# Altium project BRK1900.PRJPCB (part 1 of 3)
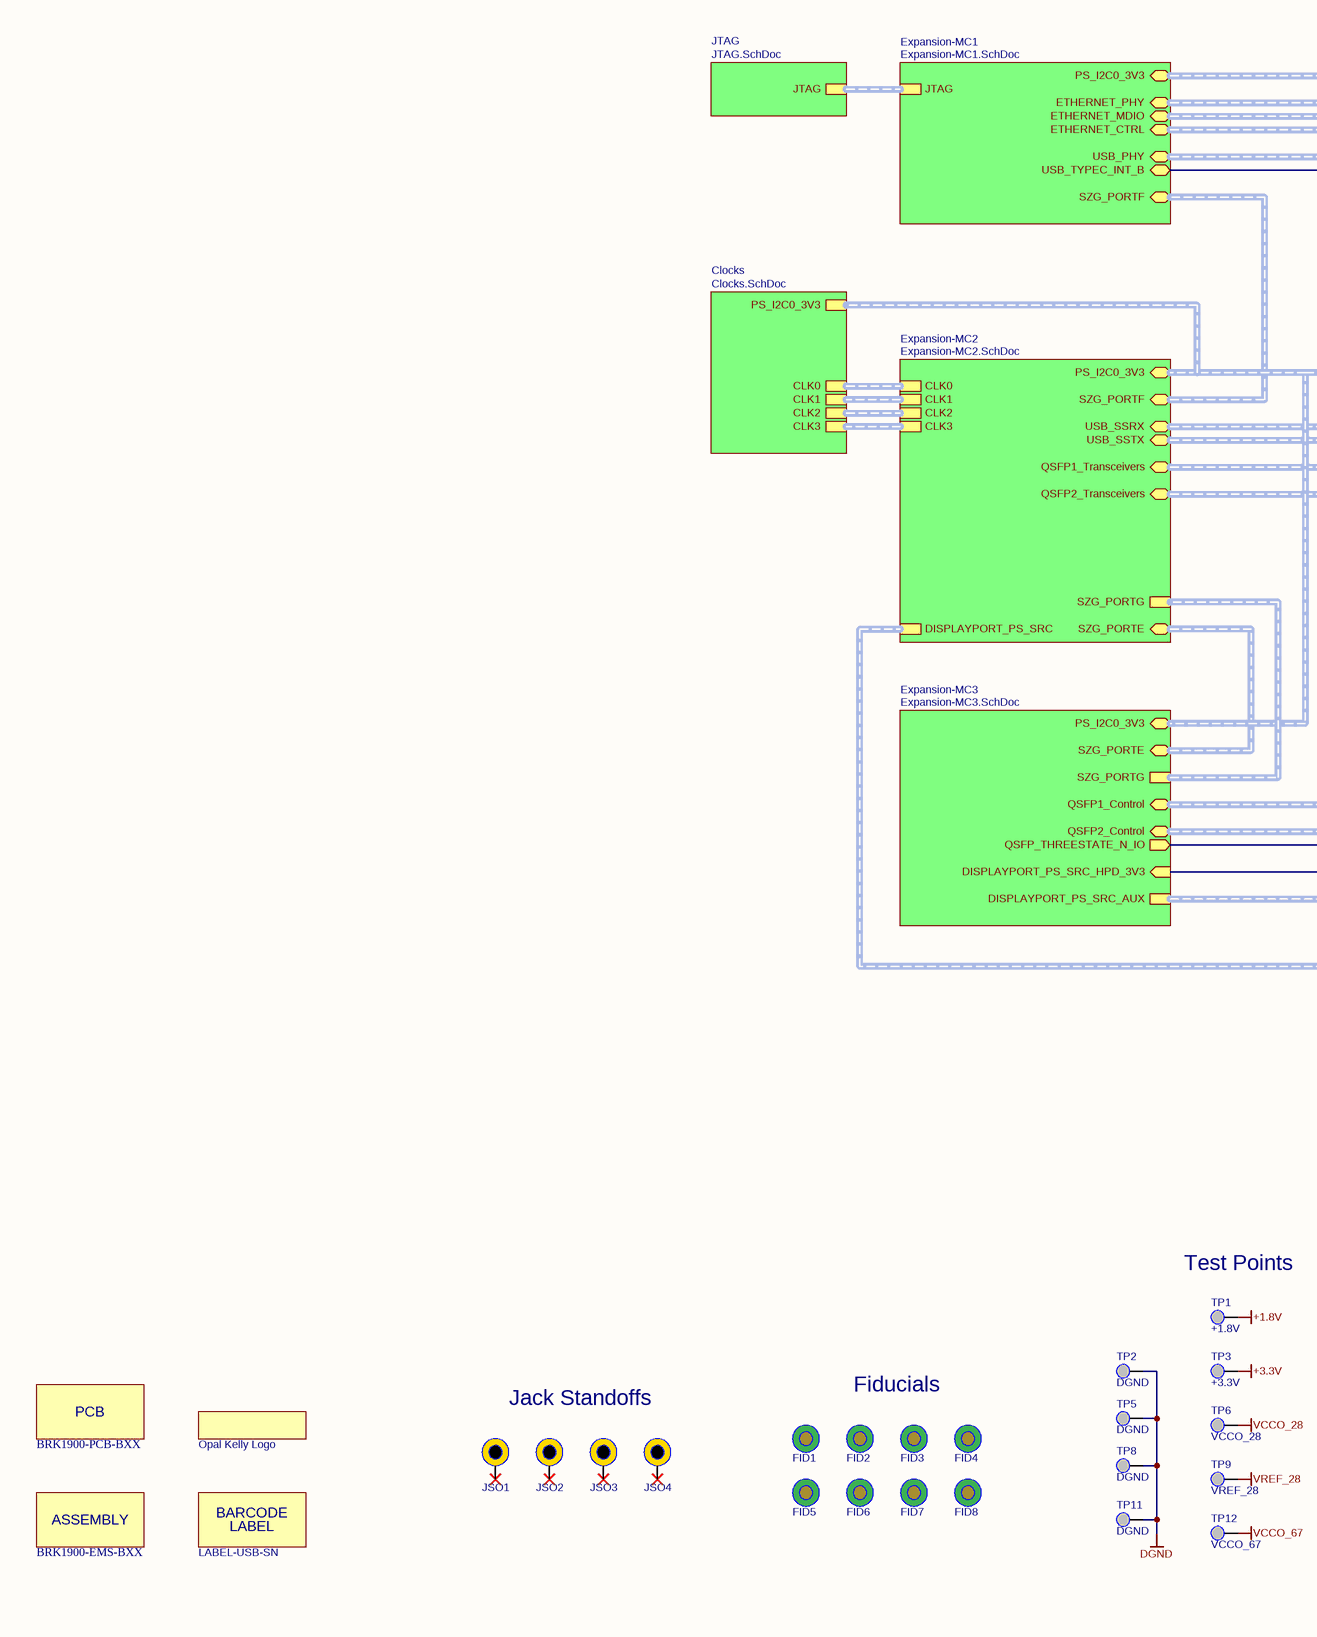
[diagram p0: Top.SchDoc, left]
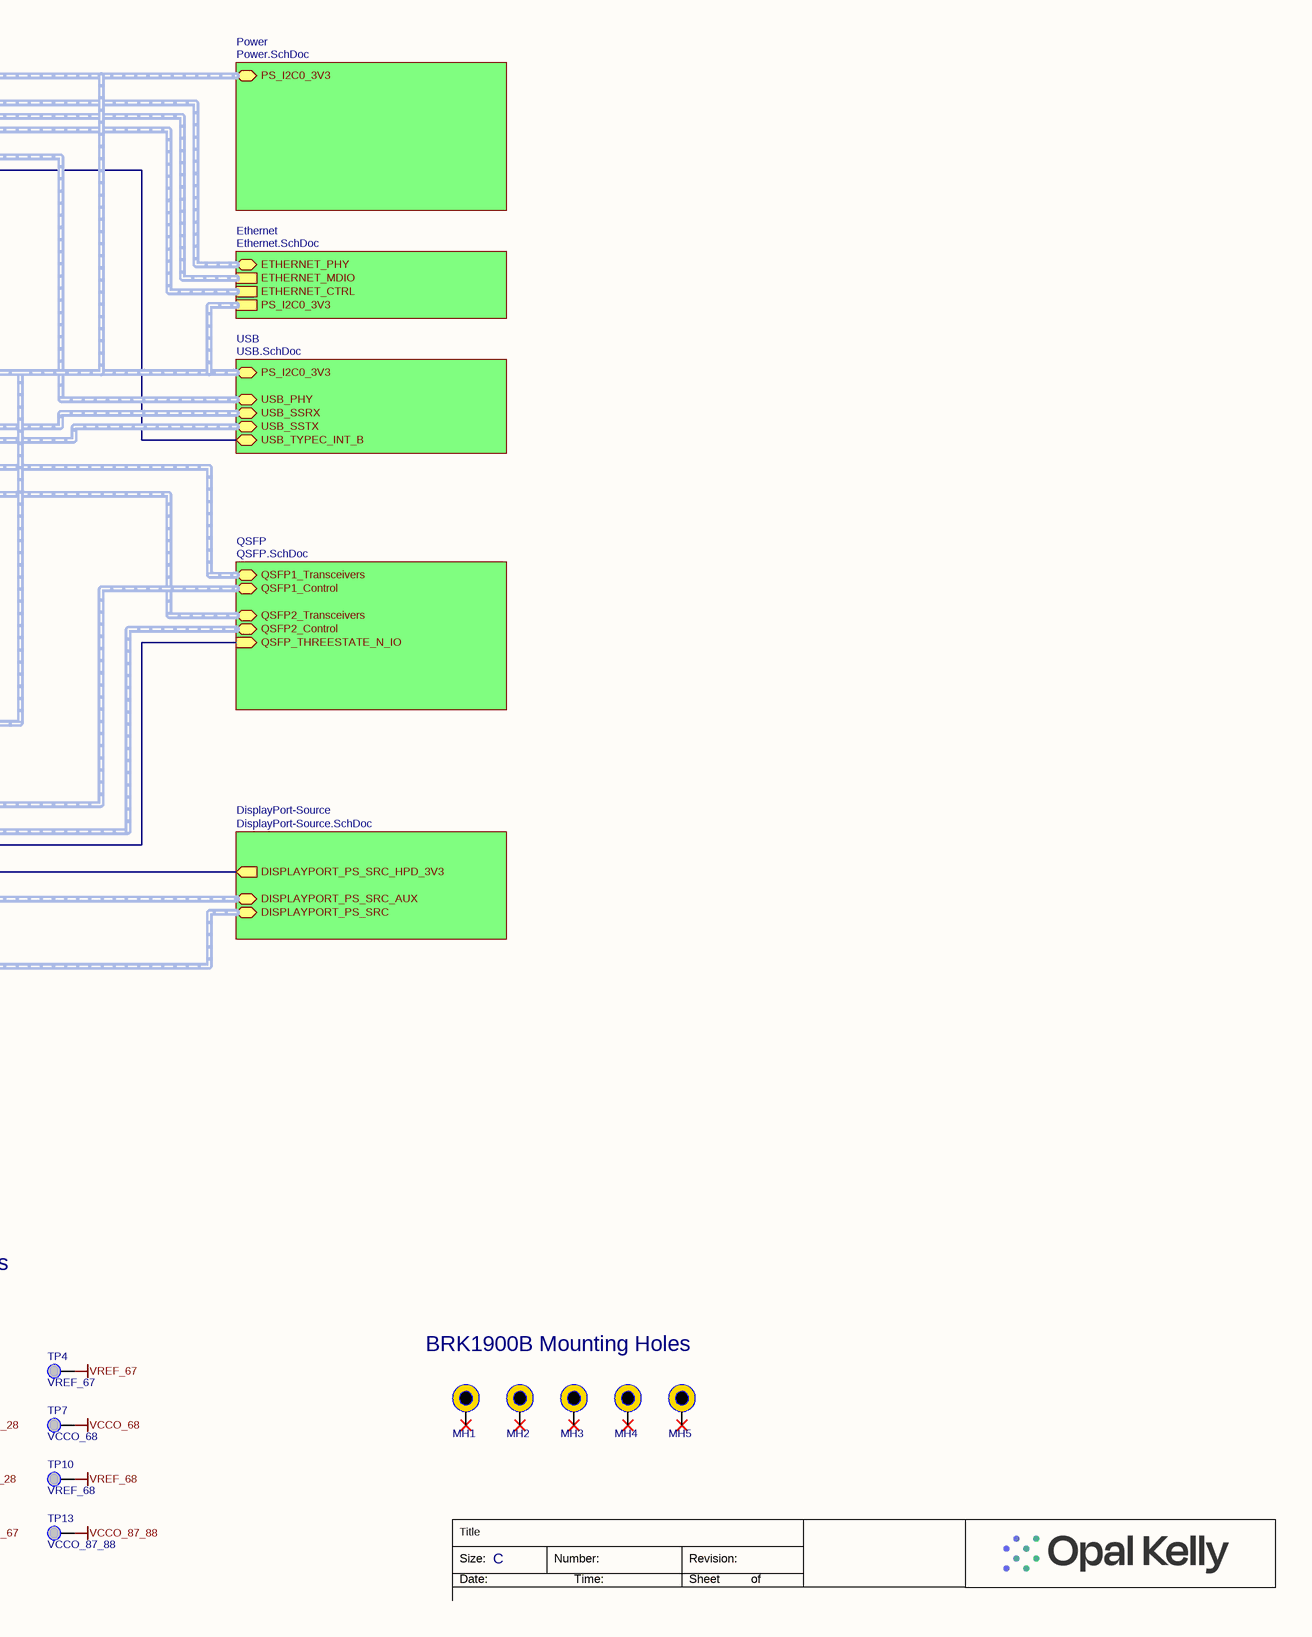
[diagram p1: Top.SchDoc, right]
BOM_Revision: 07; Part_Number: BRK1900; PCB_Revision: B
11 sheets, 459 parts. Net scope: hierarchical (ports join the sheet entries above them; power ports are global).
Board file: BRK1900.PcbDoc
Sheets:
  Top.SchDoc
    USB = USB.SchDoc
    QSFP = QSFP.SchDoc
    Expansion-MC1 = Expansion-MC1.SchDoc
    Expansion-MC2 = Expansion-MC2.SchDoc
    Expansion-MC3 = Expansion-MC3.SchDoc
    Power = Power.SchDoc
    Ethernet = Ethernet.SchDoc
    Clocks = Clocks.SchDoc
    DisplayPort-Source = DisplayPort-Source.SchDoc
    JTAG = JTAG.SchDoc

## Sheet Top.SchDoc: BRK1900 - Top Level
size C; Organization: Opal Kelly; Address1: 13500 SW 72nd Ave STE 100; Address2: Portland, OR  97223; Address3: 217.391.3724; Address4: http://www.opalkelly.com; DocumentNumber: 1; Revision: 1; SheetNumber: 1; SheetTotal: 11; PageSetup: Record=PageOptions¦CenterHorizontal=True¦CenterVertical=True¦PrintScale=0.52¦XCorrection=1.00¦YCorrection=1.00¦PrintKind=0¦BorderSize=5000000¦LeftOffset=0¦BottomOffset=0¦Orientation=2¦PaperLength=1000¦PaperWidth=1000¦Scale=100¦PaperSource=15¦PrintQuality=600¦MediaType=1¦DitherType=10¦PaperKind=Letter¦PrintScaleMode=1

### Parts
*1  Opal Kelly Logo  [okLogo-23x5-2021]
ASSY1  BRK1900-EMS-BXX  (mechanical)
FID1  FIDUCIAL  [FID1MM/2MM-SS]  (value not drawn)
FID2  FIDUCIAL  [FID1MM/2MM-SS]  (value not drawn)
FID3  FIDUCIAL  [FID1MM/2MM-SS]  (value not drawn)
FID4  FIDUCIAL  [FID1MM/2MM-SS]  (value not drawn)
FID5  FIDUCIAL  [FID1MM/2MM-SS]  (value not drawn)
FID6  FIDUCIAL  [FID1MM/2MM-SS]  (value not drawn)
FID7  FIDUCIAL  [FID1MM/2MM-SS]  (value not drawn)
FID8  FIDUCIAL  [FID1MM/2MM-SS]  (value not drawn)
JSO1  Jack Screw Standoff  [JSO-0515-01]  (value not drawn)
JSO2  Jack Screw Standoff  [JSO-0515-01]  (value not drawn)
JSO3  Jack Screw Standoff  [JSO-0515-01]  (value not drawn)
JSO4  Jack Screw Standoff  [JSO-0515-01]  (value not drawn)
LABEL1  LABEL-USB-SN  (mechanical)
MH1  MTG  [MTG-3.2/6.5-PTH]  (value not drawn)
MH2  MTG  [MTG-3.2/6.5-PTH]  (value not drawn)
MH3  MTG  [MTG-3.2/6.5-PTH]  (value not drawn)
MH4  MTG  [MTG-3.2/6.5-PTH]  (value not drawn)
MH5  MTG  [MTG-3.2/6.5-PTH]  (value not drawn)
PCB1  BRK1900-PCB-BXX  (mechanical)
TP1  +1.8V  [TP-PTH-25/45]
TP2  DGND  [TP-PTH-25/45]
TP3  +3.3V  [TP-PTH-25/45]
TP4  VREF_67  [TP-PTH-25/45]
TP5  DGND  [TP-PTH-25/45]
TP6  VCCO_28  [TP-PTH-25/45]
TP7  VCCO_68  [TP-PTH-25/45]
TP8  DGND  [TP-PTH-25/45]
TP9  VREF_28  [TP-PTH-25/45]
TP10  VREF_68  [TP-PTH-25/45]
TP11  DGND  [TP-PTH-25/45]
TP12  VCCO_67  [TP-PTH-25/45]
TP13  VCCO_87_88  [TP-PTH-25/45]

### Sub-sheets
Clocks = Clocks.SchDoc: CLK0 (harness Clock), CLK1 (harness Clock), CLK2 (harness Clock), CLK3 (harness Clock), PS_I2C0_3V3 (harness I2C)
DisplayPort-Source = DisplayPort-Source.SchDoc: DISPLAYPORT_PS_SRC (bidir, harness DISPLAYPORT), DISPLAYPORT_PS_SRC_AUX (bidir, harness DIFF_PAIR), DISPLAYPORT_PS_SRC_HPD_3V3 (out)
Ethernet = Ethernet.SchDoc: ETHERNET_PHY (bidir, harness ETH_PHY), ETHERNET_MDIO (harness ETH_MDIO), ETHERNET_CTRL (harness ETH_CTRL), PS_I2C0_3V3 (harness I2C)
Expansion-MC1 = Expansion-MC1.SchDoc: USB_PHY (bidir, harness USB_PHY), PS_I2C0_3V3 (bidir, harness I2C), SZG_PORTF (bidir, harness SYZYGY_TXR4), ETHERNET_PHY (bidir, harness ETH_PHY), USB_TYPEC_INT_B (bidir), ETHERNET_MDIO (bidir, harness ETH_MDIO), ETHERNET_CTRL (bidir, harness ETH_CTRL), JTAG (harness JTAG)
Expansion-MC2 = Expansion-MC2.SchDoc: USB_SSTX (bidir, harness DIFF_PAIR), USB_SSRX (bidir, harness DIFF_PAIR), QSFP1_Transceivers (bidir, harness QSFP_Transceivers), QSFP2_Transceivers (bidir, harness QSFP_Transceivers), SZG_PORTE (bidir, harness SYZYGY_TXR4), SZG_PORTF (bidir, harness SYZYGY_TXR4), PS_I2C0_3V3 (bidir, harness I2C), CLK0 (harness Clock), CLK1 (harness Clock), CLK2 (harness Clock), CLK3 (harness Clock), SZG_PORTG (harness SYZYGY_TXR4), DISPLAYPORT_PS_SRC (harness DISPLAYPORT)
Expansion-MC3 = Expansion-MC3.SchDoc: QSFP1_Control (bidir, harness QSFP_Control), QSFP2_Control (bidir, harness QSFP_Control), SZG_PORTE (bidir, harness SYZYGY_TXR4), PS_I2C0_3V3 (bidir, harness I2C), SZG_PORTG (harness SYZYGY_TXR4), DISPLAYPORT_PS_SRC_AUX (harness DIFF_PAIR), DISPLAYPORT_PS_SRC_HPD_3V3 (in), QSFP_THREESTATE_N_IO (out)
JTAG = JTAG.SchDoc: JTAG (harness JTAG)
Power = Power.SchDoc: PS_I2C0_3V3 (bidir, harness I2C)
QSFP = QSFP.SchDoc: QSFP1_Control (bidir, harness QSFP_Control), QSFP2_Control (bidir, harness QSFP_Control), QSFP1_Transceivers (bidir, harness QSFP_Transceivers), QSFP2_Transceivers (bidir, harness QSFP_Transceivers), QSFP_THREESTATE_N_IO (in)
USB = USB.SchDoc: USB_SSRX (bidir, harness DIFF_PAIR), USB_SSTX (bidir, harness DIFF_PAIR), PS_I2C0_3V3 (bidir, harness I2C), USB_PHY (bidir, harness USB_PHY), USB_TYPEC_INT_B (bidir)

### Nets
+1.8V: TP1.1(PIN)
+3.3V: TP3.1(PIN)
DGND: TP2.1(PIN) TP5.1(PIN) TP8.1(PIN) TP11.1(PIN)
VCCO_28: TP6.1(PIN)
VCCO_67: TP12.1(PIN)
VCCO_68: TP7.1(PIN)
VCCO_87_88: TP13.1(PIN)
VREF_28: TP9.1(PIN)
VREF_67: TP4.1(PIN)
VREF_68: TP10.1(PIN)
DISPLAYPORT_PS_SRC_HPD_3V3: sheet Expansion-MC3/DISPLAYPORT_PS_SRC_HPD_3V3, sheet DisplayPort-Source/DISPLAYPORT_PS_SRC_HPD_3V3
USB_TYPEC_INT_B: sheet USB/USB_TYPEC_INT_B, sheet Expansion-MC1/USB_TYPEC_INT_B
NetMC3_48: sheet QSFP/QSFP_THREESTATE_N_IO, sheet Expansion-MC3/QSFP_THREESTATE_N_IO

Not connected (* = marked no-connect by the designer): JSO1 1*; JSO2 1*; JSO3 1*; JSO4 1*; MH1 1*; MH2 1*; MH3 1*; MH4 1*; MH5 1*

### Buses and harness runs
harness sheet Clocks/CLK0 = sheet Expansion-MC2/CLK0
harness sheet Clocks/CLK1 = sheet Expansion-MC2/CLK1
harness sheet Clocks/CLK2 = sheet Expansion-MC2/CLK2
harness sheet Clocks/CLK3 = sheet Expansion-MC2/CLK3
harness sheet Clocks/PS_I2C0_3V3 = sheet Ethernet/PS_I2C0_3V3 = sheet Expansion-MC1/PS_I2C0_3V3 = sheet Expansion-MC2/PS_I2C0_3V3 = sheet Expansion-MC3/PS_I2C0_3V3 = sheet Power/PS_I2C0_3V3 = sheet USB/PS_I2C0_3V3
harness sheet DisplayPort-Source/DISPLAYPORT_PS_SRC = sheet Expansion-MC2/DISPLAYPORT_PS_SRC
harness sheet DisplayPort-Source/DISPLAYPORT_PS_SRC_AUX = sheet Expansion-MC3/DISPLAYPORT_PS_SRC_AUX
harness sheet Ethernet/ETHERNET_CTRL = sheet Expansion-MC1/ETHERNET_CTRL
harness sheet Ethernet/ETHERNET_MDIO = sheet Expansion-MC1/ETHERNET_MDIO
harness sheet Ethernet/ETHERNET_PHY = sheet Expansion-MC1/ETHERNET_PHY
harness sheet Expansion-MC1/JTAG = sheet JTAG/JTAG
harness sheet Expansion-MC1/SZG_PORTF = sheet Expansion-MC2/SZG_PORTF
harness sheet Expansion-MC1/USB_PHY = sheet USB/USB_PHY
harness sheet Expansion-MC2/QSFP1_Transceivers = sheet QSFP/QSFP1_Transceivers
harness sheet Expansion-MC2/QSFP2_Transceivers = sheet QSFP/QSFP2_Transceivers
harness sheet Expansion-MC2/SZG_PORTE = sheet Expansion-MC3/SZG_PORTE
harness sheet Expansion-MC2/SZG_PORTG = sheet Expansion-MC3/SZG_PORTG
harness sheet Expansion-MC2/USB_SSRX = sheet USB/USB_SSRX
harness sheet Expansion-MC2/USB_SSTX = sheet USB/USB_SSTX
harness sheet Expansion-MC3/QSFP1_Control = sheet QSFP/QSFP1_Control
harness sheet Expansion-MC3/QSFP2_Control = sheet QSFP/QSFP2_Control

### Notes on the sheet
- (near TP1) Test Points
- Fiducials
- BRK1900B Mounting Holes
- Jack Standoffs
- Title
- Size:
- Date:
- C
- Number:
- Time:
- Revision:
- Sheet
- of

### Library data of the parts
*1 = OKLOGO: partnumber: ALIGNI_IGNORE
ASSY1 = 002045: BRK1900 PCB assembly; Partnumber: 002045; Manufacturer: PCB Assembly Cost
FID1-FID8 = FIDUCIAL: PCB fiducial; partnumber: ALIGNI_IGNORE
JSO1-JSO4 = 001879: Jack screw standoff, 5mm board stack height; Partnumber: 001879; manufacturer: Samtec
LABEL1 = 000605: Barcode serial number labels for USB devices; Manufacturer: Techiant; partnumber: 000605
MH1-MH5 = MTG: Mounting hole; partnumber: ALIGNI_IGNORE
PCB1 = 002035: PCB for BRK1900; Partnumber: 002035; Manufacturer: Generic PCB Manufacturer
TP1-TP13 = TP-PTH-25/45: Test point, plated through-hole, 25/45mil; partnumber: ALIGNI_IGNORE

## Sheet USB.SchDoc: BRK1900 - USB
size C; Organization: Opal Kelly; Address1: 13500 SW 72nd Ave STE 100; Address2: Portland, OR  97223; Address3: 217.391.3724; Address4: http://www.opalkelly.com; DocumentNumber: 7; Revision: 1; SheetNumber: 7; SheetTotal: 11; PageSetup: Record=PageOptions¦CenterHorizontal=True¦CenterVertical=True¦PrintScale=0.52¦XCorrection=1.00¦YCorrection=1.00¦PrintKind=0¦BorderSize=5000000¦LeftOffset=0¦BottomOffset=0¦Orientation=2¦PaperLength=1000¦PaperWidth=1000¦Scale=100¦PaperSource=7¦PrintQuality=-4¦MediaType=1¦DitherType=10¦PaperKind=Letter¦PrintScaleMode=1
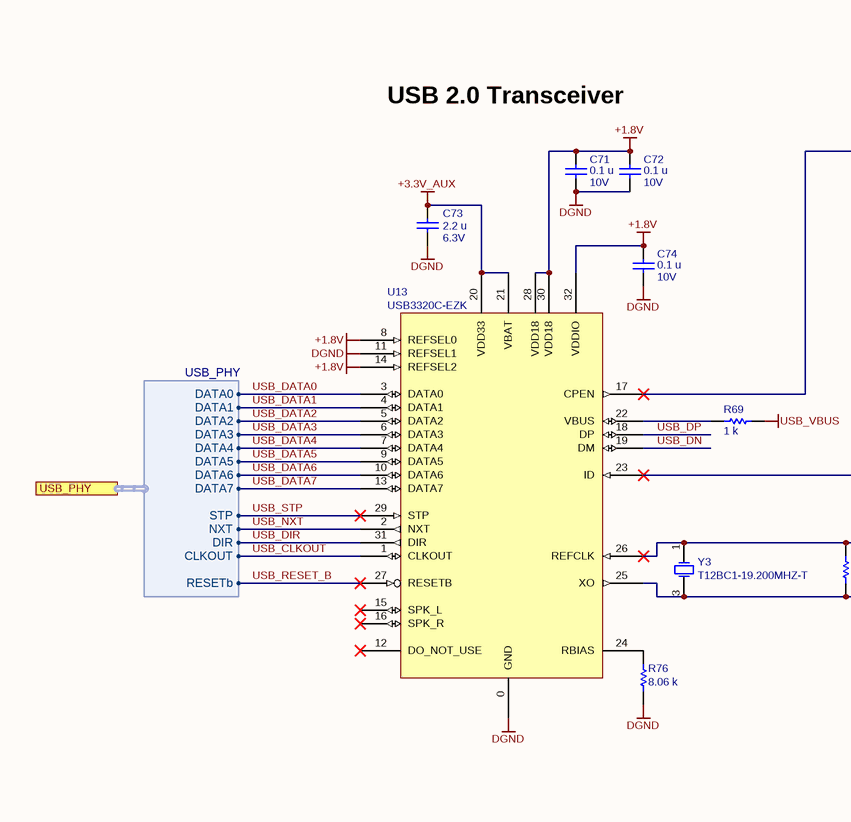
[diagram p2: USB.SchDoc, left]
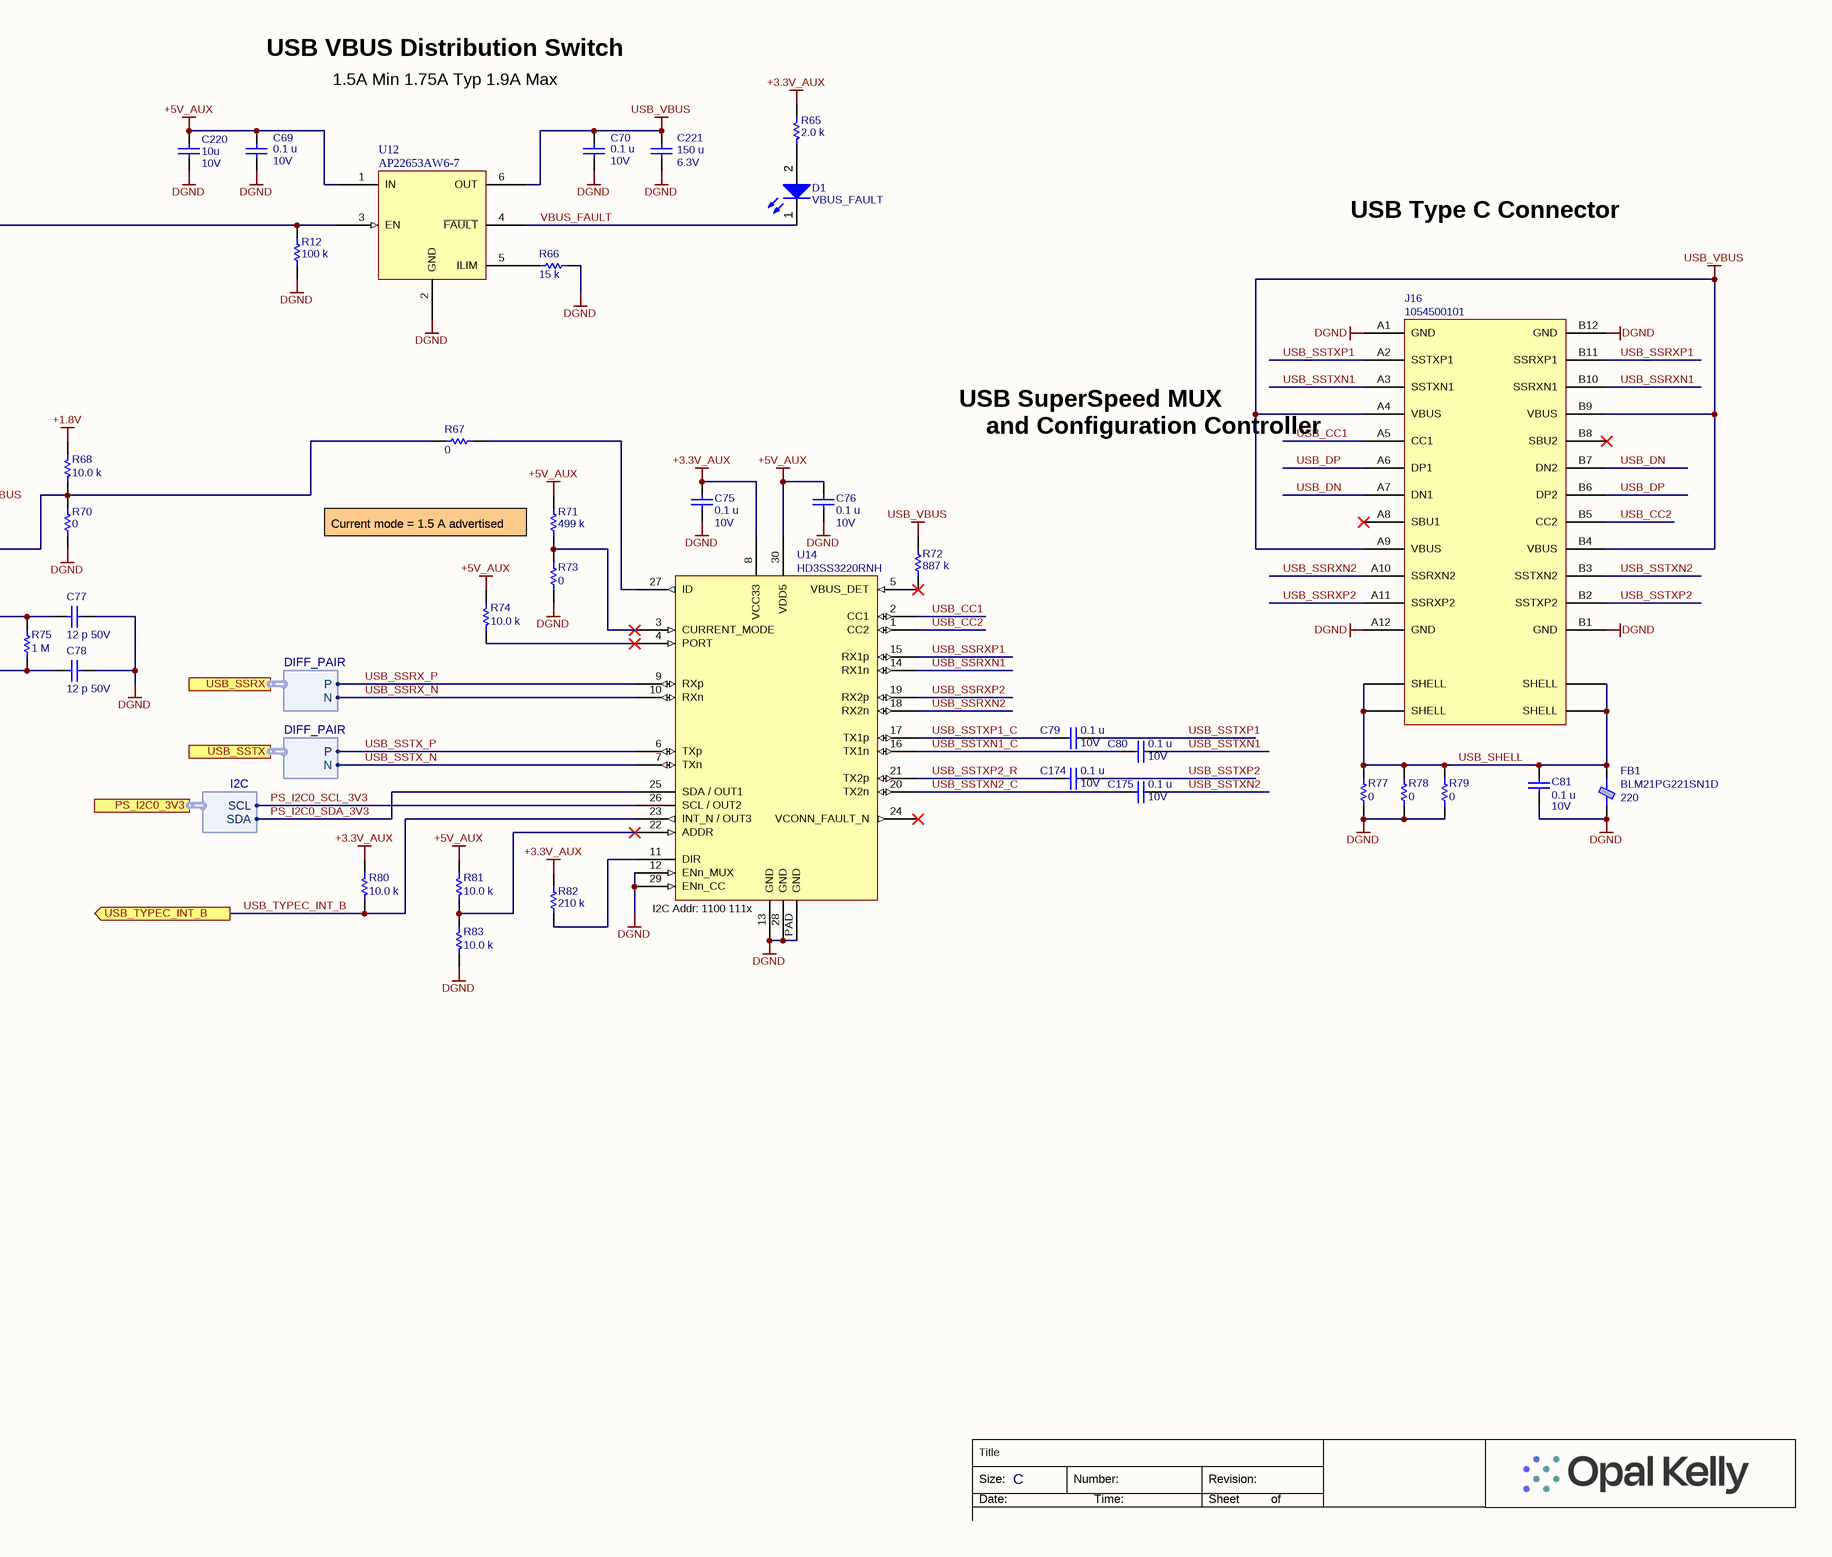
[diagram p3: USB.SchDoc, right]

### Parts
C69  value 0.1 u  Voltage: 10V  [CAPC1005X06A]  (hidden comment: C0402C104K8PACTU)
C70  value 0.1 u  Voltage: 10V  [CAPC1005X06A]  (hidden comment: C0402C104K8PACTU)
C71  value 0.1 u  Voltage: 10V  [CAPC1005X06A]  (hidden comment: C0402C104K8PACTU)
C72  value 0.1 u  Voltage: 10V  [CAPC1005X06A]  (hidden comment: C0402C104K8PACTU)
C73  value 2.2 u  Voltage: 6.3V  [CAPC1005X06A]  (hidden comment: CL05A225KQ5NNNC)
C74  value 0.1 u  Voltage: 10V  [CAPC1005X06A]  (hidden comment: C0402C104K8PACTU)
C75  value 0.1 u  Voltage: 10V  [CAPC1005X06A]  (hidden comment: C0402C104K8PACTU)
C76  value 0.1 u  Voltage: 10V  [CAPC1005X06A]  (hidden comment: C0402C104K8PACTU)
C77  value 12 p  Voltage: 50V  [CAPC1005X06A]  (hidden comment: C0402C120J5GACTU)
C78  value 12 p  Voltage: 50V  [CAPC1005X06A]  (hidden comment: C0402C120J5GACTU)
C79  value 0.1 u  Voltage: 10V  [CAPC1005X06A]  (hidden comment: C0402C104K8PACTU)
C80  value 0.1 u  Voltage: 10V  [CAPC1005X06A]  (hidden comment: C0402C104K8PACTU)
C81  value 0.1 u  Voltage: 10V  [CAPC1005X06A]  (hidden comment: C0402C104K8PACTU)
C174  value 0.1 u  Voltage: 10V  [CAPC1005X06A]  (hidden comment: C0402C104K8PACTU)
C175  value 0.1 u  Voltage: 10V  [CAPC1005X06A]  (hidden comment: C0402C104K8PACTU)
C220  value 10u  Voltage: 10V  [CAPC1608X09N]  (hidden comment: LMK107BJ106MALTD)
C221  value 150 u  Voltage: 6.3V  [CAPC3216N]  (hidden comment: GRM31CR60J157ME11L)
D1  VBUS_FAULT  [CD1608-0603-PIN1-CATHODE]
FB1  BLM21PG221SN1D  value 220  [RESC2012N]
J16  1054500101  [1054500101]
R12  value 100 k  [RESC1005X06A]  (hidden comment: CRCW0402100KFKED)
R65  value 2.0 k  [RESC1005X06A]  (hidden comment: CRCW04022K00FKED)
R66  value 15 k  [RESC1005X06A]  (hidden comment: CRCW040215K0FKED)
R67  value 0  [RESC1005X06A]  (hidden comment: CRCW04020000Z0ED)
R68  value 10.0 k  [RESC1005X06A]  (hidden comment: CRCW040210K0FKED)
R69  value 1 k  [RESC1005X06A]  (hidden comment: CRCW04021K00FKED)
R70  value 0  [RESC1005X06A]  (hidden comment: CRCW04020000Z0ED)
R71  value 499 k  [RESC1005X06A]  (hidden comment: CRCW0402499KFKEDC)
R72  value 887 k  [RESC1005X06A]  (hidden comment: CRCW0402887KFKED)
R73  value 0  [RESC1005X06A]  (hidden comment: CRCW04020000Z0ED)
R74  value 10.0 k  [RESC1005X06A]  (hidden comment: CRCW040210K0FKED)
R75  value 1 M  [RESC1005X06A]  (hidden comment: CRCW04021M00JNED)
R76  value 8.06 k  [RESC1005X06A]  (hidden comment: CRCW04028K06FKED)
R77  value 0  [RESC1005X06A]  (hidden comment: CRCW04020000Z0ED)
R78  value 0  [RESC1005X06A]  (hidden comment: CRCW04020000Z0ED)
R79  value 0  [RESC1005X06A]  (hidden comment: CRCW04020000Z0ED)
R80  value 10.0 k  [RESC1005X06A]  (hidden comment: CRCW040210K0FKED)
R81  value 10.0 k  [RESC1005X06A]  (hidden comment: CRCW040210K0FKED)
R82  value 210 k  [RESC1005X06A]  (hidden comment: CRCW0402210KFKED)
R83  value 10.0 k  [RESC1005X06A]  (hidden comment: CRCW040210K0FKED)
U12  AP22653AW6-7  [AP2265XW6]
U13  USB3320C-EZK  [QFN-32]
U14  HD3SS3220RNH  [WQFN-30]
Y3  T12BC1-19.200MHZ-T  [OSC_SMD_32x25]

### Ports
PS_I2C0_3V3 (harness I2C), USB_PHY (harness USB_PHY), USB_SSRX (harness DIFF_PAIR), USB_SSTX (harness DIFF_PAIR), USB_TYPEC_INT_B (out)

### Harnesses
USB_PHY: DATA0, DATA1, DATA2, DATA3, DATA4, DATA5, DATA6, DATA7, STP, NXT, DIR, CLKOUT, RESETb
I2C: SCL, SDA
DIFF_PAIR: P, N

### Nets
+1.8V: C71.2 C72.2 C74.2 R68.2 U13.8(REFSEL0) U13.14(REFSEL2) U13.28(VDD18) U13.30(VDD18) U13.32(VDDIO)
+3.3V_AUX: C73.2 C75.2 R65.2 R80.2 R82.2 U13.20(VDD33) U13.21(VBAT) U14.8(VCC33)
+5V_AUX: C69.2 C76.2 C220.2 R71.2 R74.2 R81.2 U12.1(IN) U14.30(VDD5)
DGND: C69.1 C70.1 C71.1 C72.1 C73.1 C74.1 C75.1 C76.1 C77.1 C78.1 C81.1 C220.1 C221.1 FB1.2 J16.A1(GND) J16.A12(GND) J16.B1(GND) J16.B12(GND) R12.2 R66.1 R70.2 R73.2 R76.1 R77.2 R78.2 R79.2 R83.1 U12.2(GND) U13.0(GND) U13.11(REFSEL1) U14.12(ENn_MUX) U14.13(GND) U14.28(GND) U14.29(ENn_CC) U14.PAD(GND)
USB_VBUS: C70.2 C221.2 J16.A4(VBUS) J16.A9(VBUS) J16.B4(VBUS) J16.B9(VBUS) R69.1 R72.2 U12.6(OUT)
PS_I2C0_SCL_3V3: U14.26(SCL_/_OUT2) ; port PS_I2C0_3V3.SCL
PS_I2C0_SDA_3V3: U14.25(SDA_/_OUT1) ; port PS_I2C0_3V3.SDA
USB_CC1: J16.A5(CC1) U14.2(CC1)
USB_CC2: J16.B5(CC2) U14.1(CC2)
USB_CLKOUT: U13.1(CLKOUT) ; port USB_PHY.CLKOUT
USB_DATA0: U13.3(DATA0) ; port USB_PHY.DATA0
USB_DATA1: U13.4(DATA1) ; port USB_PHY.DATA1
USB_DATA2: U13.5(DATA2) ; port USB_PHY.DATA2
USB_DATA3: U13.6(DATA3) ; port USB_PHY.DATA3
USB_DATA4: U13.7(DATA4) ; port USB_PHY.DATA4
USB_DATA5: U13.9(DATA5) ; port USB_PHY.DATA5
USB_DATA6: U13.10(DATA6) ; port USB_PHY.DATA6
USB_DATA7: U13.13(DATA7) ; port USB_PHY.DATA7
USB_DIR: U13.31(DIR) ; port USB_PHY.DIR
USB_DN: J16.A7(DN1) J16.B7(DN2) U13.19(DM)
USB_DP: J16.A6(DP1) J16.B6(DP2) U13.18(DP)
USB_NXT: U13.2(NXT) ; port USB_PHY.NXT
USB_RESET_B: U13.27(RESETB) ; port USB_PHY.RESETb
USB_SHELL: C81.2 FB1.1 J16.M1(SHELL) J16.M2(SHELL) J16.M3(SHELL) J16.M4(SHELL) R77.1 R78.1 R79.1
USB_SSRX_N: U14.10(RXn) ; port USB_SSRX.N
USB_SSRX_P: U14.9(RXp) ; port USB_SSRX.P
USB_SSRXN1: J16.B10(SSRXN1) U14.14(RX1n)
USB_SSRXN2: J16.A10(SSRXN2) U14.18(RX2n)
USB_SSRXP1: J16.B11(SSRXP1) U14.15(RX1p)
USB_SSRXP2: J16.A11(SSRXP2) U14.19(RX2p)
USB_SSTX_N: U14.7(TXn) ; port USB_SSTX.N
USB_SSTX_P: U14.6(TXp) ; port USB_SSTX.P
USB_SSTXN1: C80.2 J16.A3(SSTXN1)
USB_SSTXN1_C: C80.1 U14.16(TX1n)
USB_SSTXN2: C175.2 J16.B3(SSTXN2)
USB_SSTXN2_C: C175.1 U14.20(TX2n)
USB_SSTXP1: C79.2 J16.A2(SSTXP1)
USB_SSTXP1_C: C79.1 U14.17(TX1p)
USB_SSTXP2: C174.2 J16.B2(SSTXP2)
USB_SSTXP2_R: C174.1 U14.21(TX2p)
USB_STP: U13.29(STP) ; port USB_PHY.STP
USB_TYPEC_INT_B: R80.1 U14.23(INT_N_/_OUT3) ; port USB_TYPEC_INT_B
VBUS_FAULT: D1.1(K) U12.4(~{FAULT})
NetC77_2: C77.2 R75.2 U13.26(REFCLK) Y3.1(OSC1)
NetC78_2: C78.2 R75.1 U13.25(XO) Y3.3(OSC2)
NetD1_2: D1.2(A) R65.1
NetR12_1: R12.1 U12.3(EN) U13.17(CPEN)
NetR66_2: R66.2 U12.5(ILIM)
NetR67_1: R67.1 R68.1 R70.1 U13.23(ID)
NetR67_2: R67.2 U14.27(ID)
NetR69_2: R69.2 U13.22(VBUS)
NetR71_1: R71.1 R73.1 U14.3(CURRENT_MODE)
NetR72_1: R72.1 U14.5(VBUS_DET)
NetR74_1: R74.1 U14.4(PORT)
NetR76_2: R76.2 U13.24(RBIAS)
NetR81_1: R81.1 R83.2 U14.22(ADDR)
NetR82_1: R82.1 U14.11(DIR)

Not connected (* = marked no-connect by the designer): J16 A8(SBU1)* B8(SBU2)*; U13 12(DO_NOT_USE)* 15(SPK_L)* 16(SPK_R)* J1(NC) J9(NC) L1(NC) L9(NC) M7(NC) T7(NC); U14 24(VCONN_FAULT_N)*

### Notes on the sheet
- USB VBUS Distribution Switch
- 1.5A Min 1.75A Typ 1.9A Max
- USB 2.0 Transceiver
- USB Type C Connector
- USB SuperSpeed MUX
- and Configuration Controller
- Current mode = 1.5 A advertised
- (near U14) I2C Addr: 1100 111x
- Title
- Size:
- Date:
- C
- Number:
- Time:
- Revision:
- Sheet
- of

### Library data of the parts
C69-C72 C74 = 000070: Ceramic capacitor; Manufacturer: Kemet; partnumber: 000070; ValueFloat: 1E-7; x_tolerance: 10
C73 = 001791: Ceramic Capacitor; Partnumber: 001791; Manufacturer: Samsung Electro-Mechanics; ValueFloat: 2.2E-6; Tolerance (%): 10; Description 2: 0402, 6.3V, 10%
C75 C76 C79-C81 C174 C175 = 000070: Partnumber: 000070; manufacturer: Kemet; ValueFloat: 1E-7; x_tolerance: 10
C77 C78 = 000808: Ceramic capacitor; Manufacturer: Kemet; partnumber: 000808; ValueFloat: 1.2E-11; x_tolerance: 5
C220 = 001346: Partnumber: 001346; manufacturer: Taiyo Yuden; ValueFloat: 1E-5; x_tolerance: 20
C221 = 001785: Ceramic Capacitor; Partnumber: 001785; Manufacturer: Murata; ValueFloat: 0.00015; Tolerance (%): 20; Description 2: 1206, 6.3V
D1 = 001432: LED; Manufacturer: Dialight; Manufacturer_PN: 598-8010-107F; partnumber: 001432
FB1 = 000783: Ferrite Chip; Manufacturer: Murata; partnumber: 000783
J16 = 001907: Partnumber: 001907; manufacturer: Molex
R12 = 001070: Partnumber: 001070; manufacturer: Vishay; ValueFloat: 100000; x_tolerance: 1
R65 = 001162: Partnumber: 001162; manufacturer: Vishay; ValueFloat: 2000; x_tolerance: 1
R66 = 001121: Partnumber: 001121; manufacturer: Vishay; ValueFloat: 15000; x_tolerance: 1
R67 R70 R73 R77-R79 = 000755: Thick-film resistor; Manufacturer: Vishay; partnumber: 000755; x_tolerance: 1
R68 R74 R80 R81 R83 = 001521: Thick-film resistor; Manufacturer: Vishay; partnumber: 001521; ValueFloat: 10000; x_tolerance: 1
R69 = 000797: Thick-film resistor; Manufacturer: Vishay; partnumber: 000797; ValueFloat: 1000; x_tolerance: 1
R71 = 001945: Partnumber: 001945; manufacturer: Vishay; ValueFloat: 499000; x_tolerance: 1
R72 = 001853: Partnumber: 001853; manufacturer: Vishay; ValueFloat: 887000; x_tolerance: 1
R75 = 000800: Thick-film resistor; Manufacturer: Vishay; partnumber: 000800; ValueFloat: 1000000; x_tolerance: 5
R76 = 001266: Thick-film resistor; Manufacturer: Vishay; partnumber: 001266; ValueFloat: 8060; x_tolerance: 1
R82 = 001549: Partnumber: 001549; manufacturer: Vishay; ValueFloat: 210000; x_tolerance: 1
U12 = 002224: Load Switch with Adjustable Current Limit, Latching; Partnumber: 002224; Manufacturer: Diodes Incorporated; Description 2: 3V - 5.5V, 125mA to 2665mA Limit, Fault Out
U13 = 001262: Hi-Speed USB PHY with ULPI interface; Manufacturer: Microchip; partnumber: 001262
U14 = 001944: Partnumber: 001944; manufacturer: Texas Instruments
Y3 = 000770: Crystal; Manufacturer: MMD Monitor / Quartztek; partnumber: 000770

## Sheet QSFP.SchDoc: BRK1900 - QSFP
size C; Organization: Opal Kelly; Address1: 13500 SW 72nd Ave STE 100; Address2: Portland, OR  97223; Address3: 217.391.3724; Address4: http://www.opalkelly.com; DocumentNumber: 5; Revision: 1; SheetNumber: 5; SheetTotal: 11; PageSetup: Record=PageOptions¦CenterHorizontal=True¦CenterVertical=True¦PrintScale=0.52¦XCorrection=1.00¦YCorrection=1.00¦PrintKind=0¦BorderSize=5000000¦LeftOffset=0¦BottomOffset=0¦Orientation=2¦PaperLength=1000¦PaperWidth=1000¦Scale=100¦PaperSource=7¦PrintQuality=-4¦MediaType=1¦DitherType=10¦PaperKind=Letter¦PrintScaleMode=1
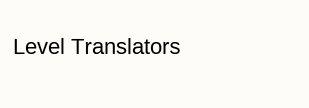
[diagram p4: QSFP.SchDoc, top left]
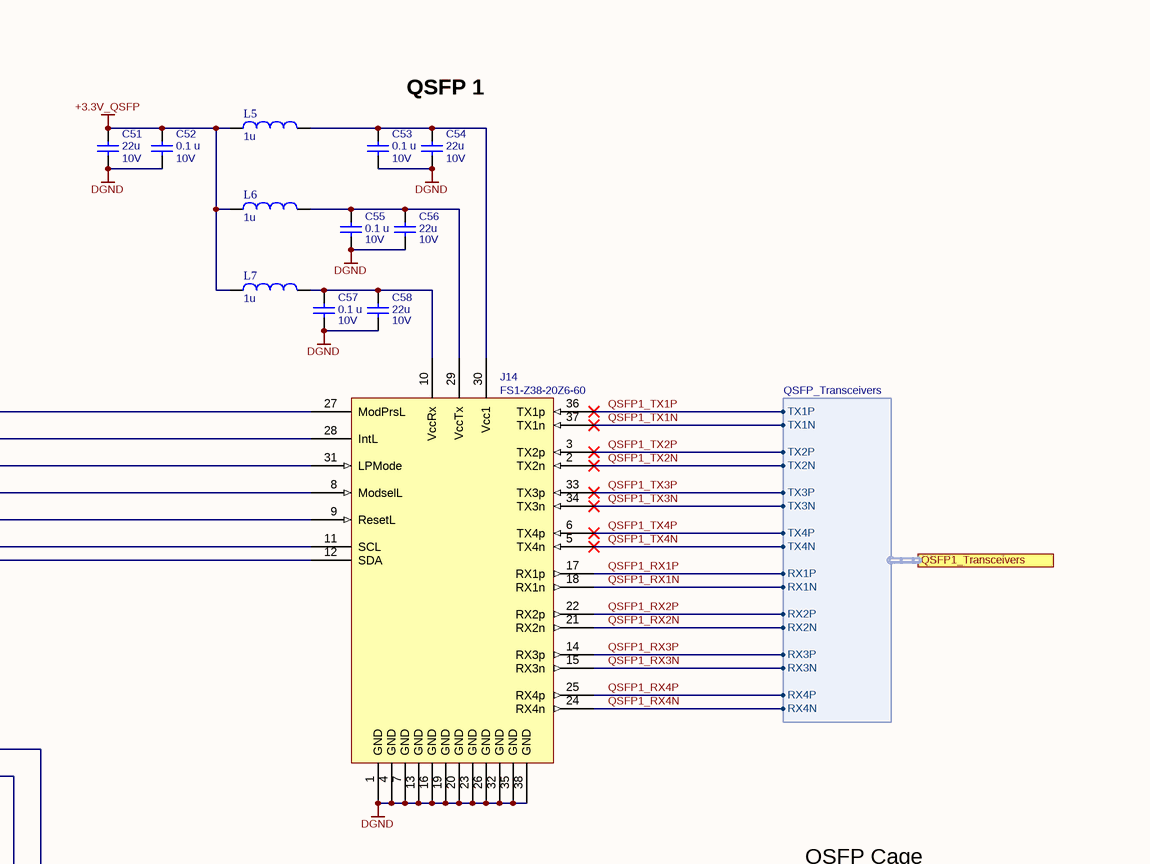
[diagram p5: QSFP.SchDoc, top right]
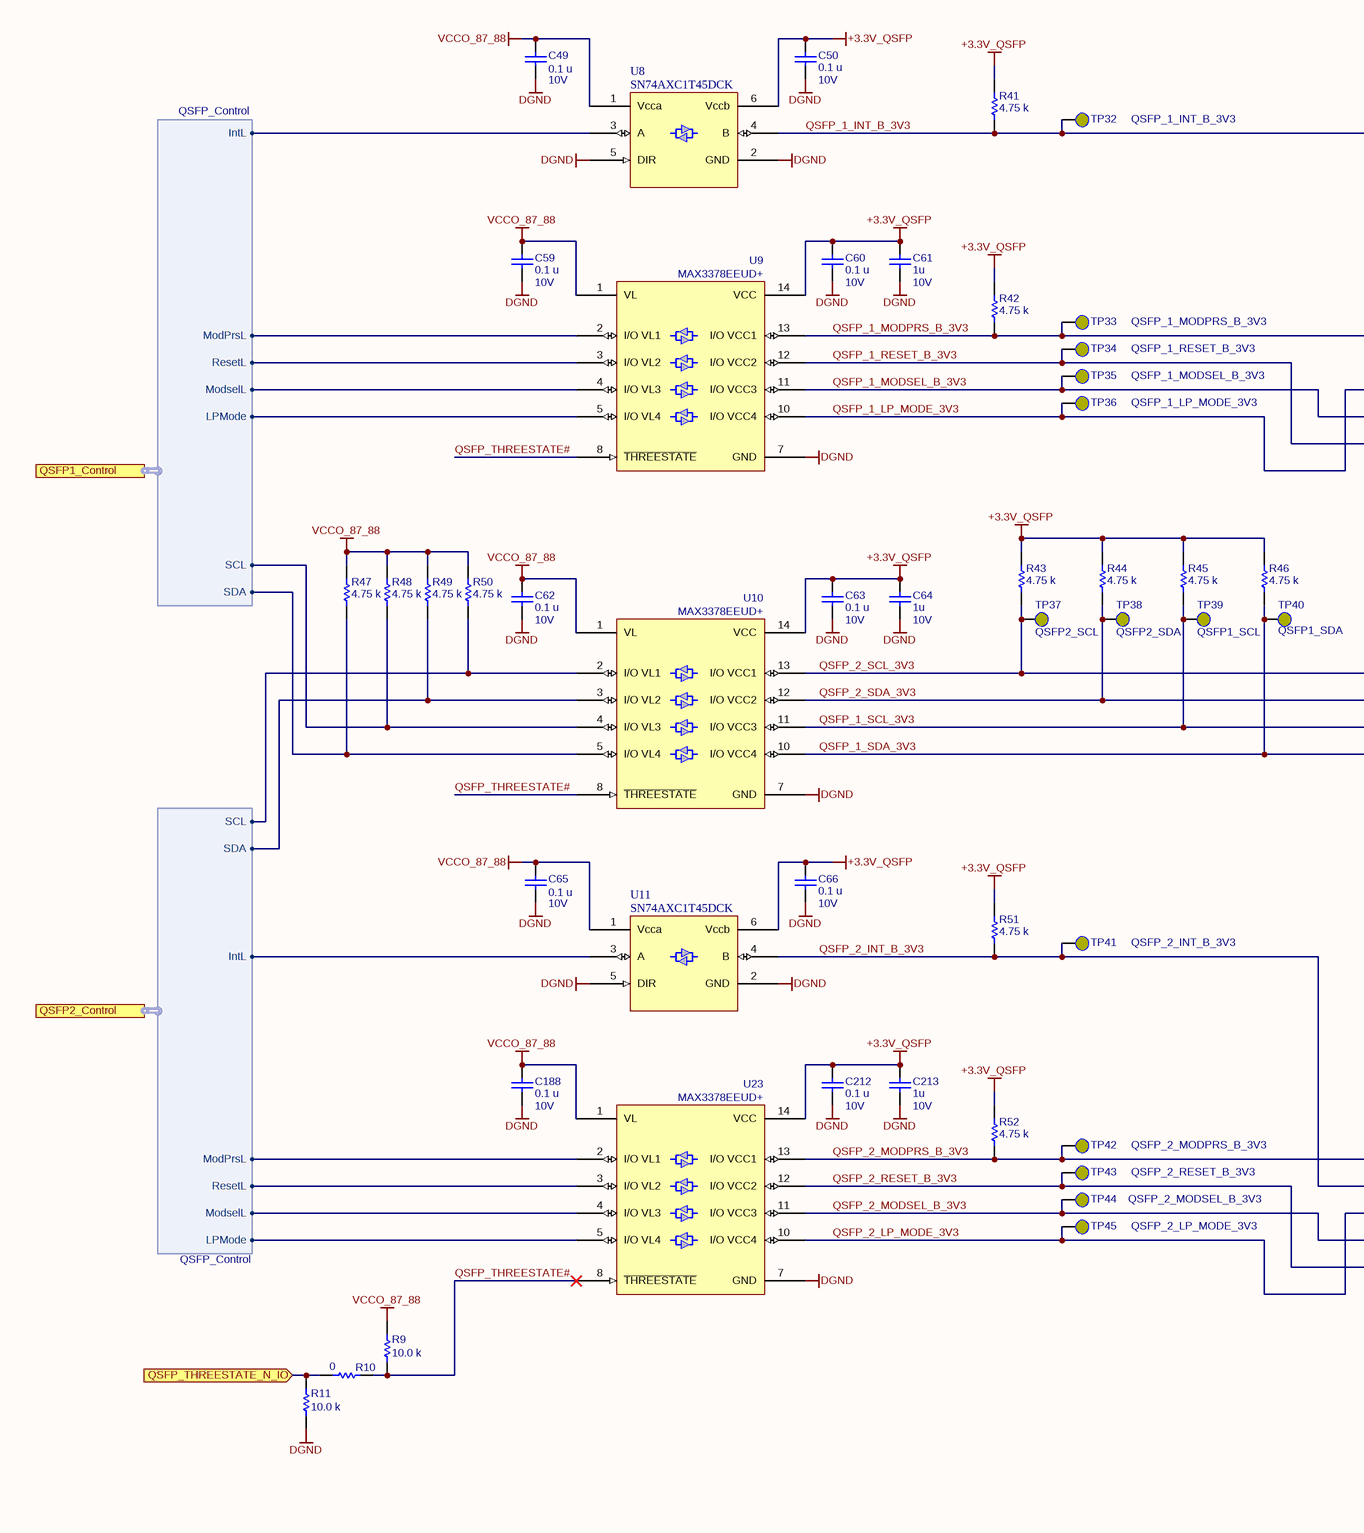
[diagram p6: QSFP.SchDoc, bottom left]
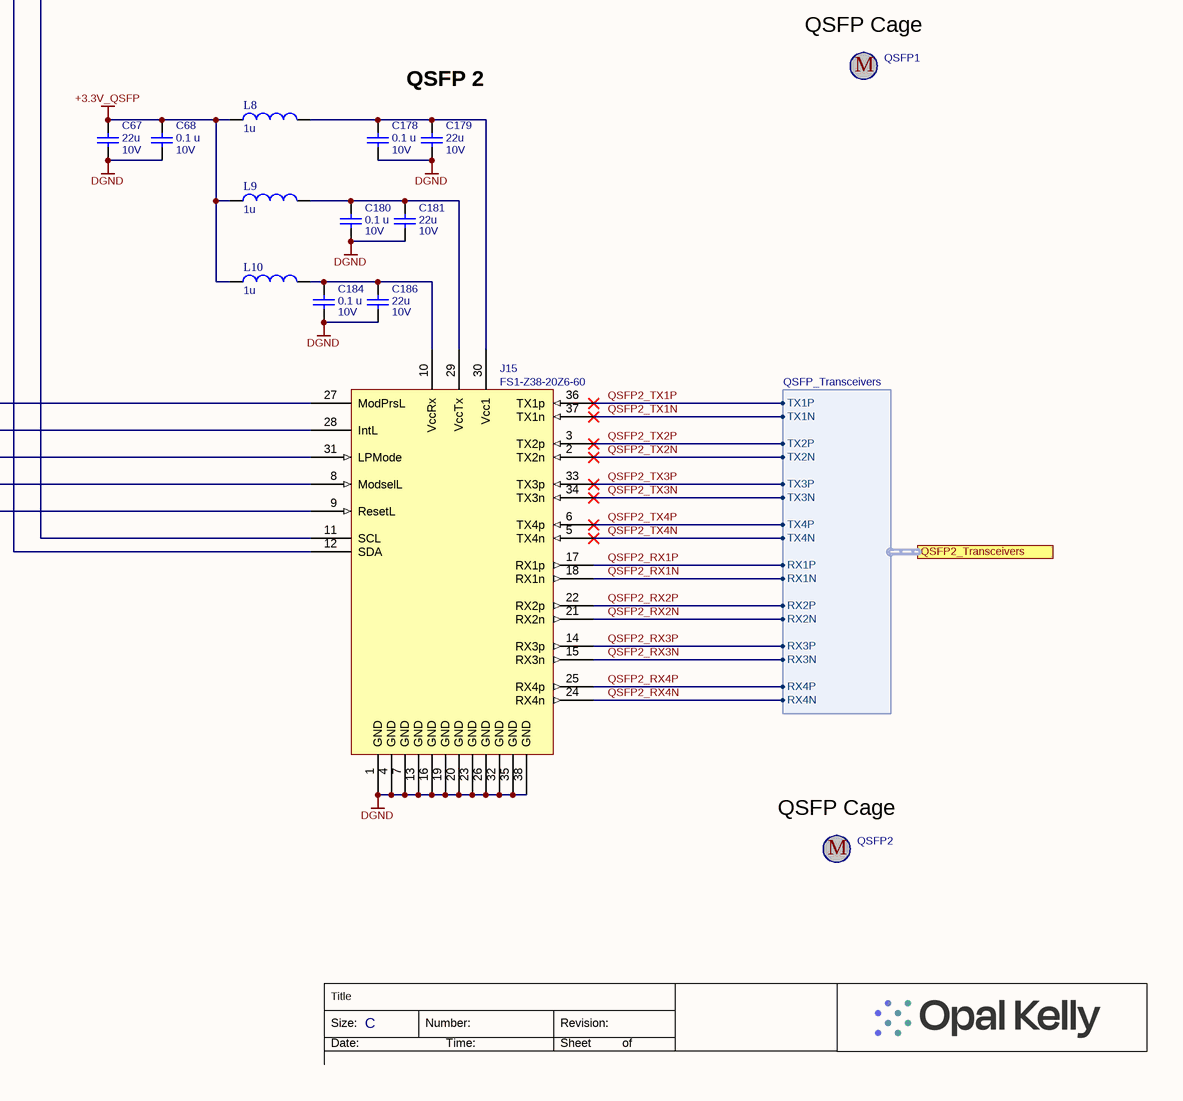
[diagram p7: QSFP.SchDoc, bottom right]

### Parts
C49  value 0.1 u  Voltage: 10V  [CAPC1005X06A]  (hidden comment: C0402C104K8PACTU)
C50  value 0.1 u  Voltage: 10V  [CAPC1005X06A]  (hidden comment: C0402C104K8PACTU)
C51  value 22u  Voltage: 10V  [CAPC3216N]  (hidden comment: SM-1206, 10%, 10v, X7R)
C52  value 0.1 u  Voltage: 10V  [CAPC1005X06A]  (hidden comment: SM-0402, 10%, 10v)
C53  value 0.1 u  Voltage: 10V  [CAPC1005X06A]  (hidden comment: SM-0402, 10%, 10v)
C54  value 22u  Voltage: 10V  [CAPC3216N]  (hidden comment: SM-1206, 10%, 10v, X7R)
C55  value 0.1 u  Voltage: 10V  [CAPC1005X06A]  (hidden comment: SM-0402, 10%, 10v)
C56  value 22u  Voltage: 10V  [CAPC3216N]  (hidden comment: SM-1206, 10%, 10v, X7R)
C57  value 0.1 u  Voltage: 10V  [CAPC1005X06A]  (hidden comment: SM-0402, 10%, 10v)
C58  value 22u  Voltage: 10V  [CAPC3216N]  (hidden comment: SM-1206, 10%, 10v, X7R)
C59  value 0.1 u  Voltage: 10V  [CAPC1005X06A]  (hidden comment: C0402C104K8PACTU)
C60  value 0.1 u  Voltage: 10V  [CAPC1005X06A]  (hidden comment: C0402C104K8PACTU)
C61  value 1u  Voltage: 10V  [CAPC1005X06A]  (hidden comment: LMK105BJ105KV-F)
C62  value 0.1 u  Voltage: 10V  [CAPC1005X06A]  (hidden comment: C0402C104K8PACTU)
C63  value 0.1 u  Voltage: 10V  [CAPC1005X06A]  (hidden comment: C0402C104K8PACTU)
C64  value 1u  Voltage: 10V  [CAPC1005X06A]  (hidden comment: LMK105BJ105KV-F)
C65  value 0.1 u  Voltage: 10V  [CAPC1005X06A]  (hidden comment: C0402C104K8PACTU)
C66  value 0.1 u  Voltage: 10V  [CAPC1005X06A]  (hidden comment: C0402C104K8PACTU)
C67  value 22u  Voltage: 10V  [CAPC3216N]  (hidden comment: SM-1206, 10%, 10v, X7R)
C68  value 0.1 u  Voltage: 10V  [CAPC1005X06A]  (hidden comment: SM-0402, 10%, 10v)
C178  value 0.1 u  Voltage: 10V  [CAPC1005X06A]  (hidden comment: SM-0402, 10%, 10v)
C179  value 22u  Voltage: 10V  [CAPC3216N]  (hidden comment: SM-1206, 10%, 10v, X7R)
C180  value 0.1 u  Voltage: 10V  [CAPC1005X06A]  (hidden comment: SM-0402, 10%, 10v)
C181  value 22u  Voltage: 10V  [CAPC3216N]  (hidden comment: SM-1206, 10%, 10v, X7R)
C184  value 0.1 u  Voltage: 10V  [CAPC1005X06A]  (hidden comment: SM-0402, 10%, 10v)
C186  value 22u  Voltage: 10V  [CAPC3216N]  (hidden comment: SM-1206, 10%, 10v, X7R)
C188  value 0.1 u  Voltage: 10V  [CAPC1005X06A]  (hidden comment: C0402C104K8PACTU)
C212  value 0.1 u  Voltage: 10V  [CAPC1005X06A]  (hidden comment: C0402C104K8PACTU)
C213  value 1u  Voltage: 10V  [CAPC1005X06A]  (hidden comment: LMK105BJ105KV-F)
J14  FS1-Z38-20Z6-60  [QSFP28_RECEPTACLE_SFF-8679]
J15  FS1-Z38-20Z6-60  [QSFP28_RECEPTACLE_SFF-8679]
L5  value 1u  [CIGT252010]  (hidden comment: CIGT252010LM1R0MNE)
L6  value 1u  [CIGT252010]  (hidden comment: CIGT252010LM1R0MNE)
L7  value 1u  [CIGT252010]  (hidden comment: CIGT252010LM1R0MNE)
L8  value 1u  [CIGT252010]  (hidden comment: CIGT252010LM1R0MNE)
L9  value 1u  [CIGT252010]  (hidden comment: CIGT252010LM1R0MNE)
L10  value 1u  [CIGT252010]  (hidden comment: CIGT252010LM1R0MNE)
QSFP1  Pressfit  [QSFP28_SINGLE_CAGE]  (value not drawn)
QSFP2  Pressfit  [QSFP28_SINGLE_CAGE]  (value not drawn)
R9  value 10.0 k  [RESC1005X06A]  (hidden comment: CRCW040210K0FKED)
R10  value 0  [RESC1005X06A]  (hidden comment: SM-0402, 1%, 1/16W)
R11  value 10.0 k  [RESC1005X06A]  (hidden comment: CRCW040210K0FKED)
R41  value 4.75 k  [RESC1005X06A]  (hidden comment: CRCW04024K75FKED)
R42  value 4.75 k  [RESC1005X06A]  (hidden comment: CRCW04024K75FKED)
R43  value 4.75 k  [RESC1005X06A]  (hidden comment: CRCW04024K75FKED)
R44  value 4.75 k  [RESC1005X06A]  (hidden comment: CRCW04024K75FKED)
R45  value 4.75 k  [RESC1005X06A]  (hidden comment: CRCW04024K75FKED)
R46  value 4.75 k  [RESC1005X06A]  (hidden comment: CRCW04024K75FKED)
R47  value 4.75 k  [RESC1005X06A]  (hidden comment: CRCW04024K75FKED)
R48  value 4.75 k  [RESC1005X06A]  (hidden comment: CRCW04024K75FKED)
R49  value 4.75 k  [RESC1005X06A]  (hidden comment: CRCW04024K75FKED)
R50  value 4.75 k  [RESC1005X06A]  (hidden comment: CRCW04024K75FKED)
R51  value 4.75 k  [RESC1005X06A]  (hidden comment: CRCW04024K75FKED)
R52  value 4.75 k  [RESC1005X06A]  (hidden comment: CRCW04024K75FKED)
TP32  QSFP_1_INT_B_3V3  [TP-SMD40]
TP33  QSFP_1_MODPRS_B_3V3  [TP-SMD40]
TP34  QSFP_1_RESET_B_3V3  [TP-SMD40]
TP35  QSFP_1_MODSEL_B_3V3  [TP-SMD40]
TP36  QSFP_1_LP_MODE_3V3  [TP-SMD40]
TP37  QSFP2_SCL  [TP-SMD40]
TP38  QSFP2_SDA  [TP-SMD40]
TP39  QSFP1_SCL  [TP-SMD40]
TP40  QSFP1_SDA  [TP-SMD40]
TP41  QSFP_2_INT_B_3V3  [TP-SMD40]
TP42  QSFP_2_MODPRS_B_3V3  [TP-SMD40]
TP43  QSFP_2_RESET_B_3V3  [TP-SMD40]
TP44  QSFP_2_MODSEL_B_3V3  [TP-SMD40]
TP45  QSFP_2_LP_MODE_3V3  [TP-SMD40]
U8  SN74AXC1T45DCK  [DCK-R-PDSO-G6]
U9  MAX3378EEUD+  [MAX3378EEUD+]
U10  MAX3378EEUD+  [MAX3378EEUD+]
U11  SN74AXC1T45DCK  [DCK-R-PDSO-G6]
U23  MAX3378EEUD+  [MAX3378EEUD+]

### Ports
QSFP1_Control (harness QSFP_Control), QSFP1_Transceivers (harness QSFP_Transceivers), QSFP2_Control (harness QSFP_Control), QSFP2_Transceivers (harness QSFP_Transceivers), QSFP_THREESTATE_N_IO (in)

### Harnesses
QSFP_Transceivers: TX1P, TX1N, TX2P, TX2N, TX3P, TX3N, TX4P, TX4N, RX1P, RX1N, RX2P, RX2N, RX3P, RX3N, RX4P, RX4N
QSFP_Control: ModPrsL, IntL, LPMode, ModselL, ResetL, SCL, SDA

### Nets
+3.3V_QSFP: C50.2 C51.2 C52.2 C60.2 C61.2 C63.2 C64.2 C66.2 C67.2 C68.2 C212.2 C213.2 L5.1 L6.1 L7.1 L8.1 L9.1 L10.1 R41.2 R42.2 R43.2 R44.2 R45.2 R46.2 R51.2 R52.2 U8.6(Vccb) U9.14(VCC) U10.14(VCC) U11.6(Vccb) U23.14(VCC)
DGND: C49.1 C50.1 C51.1 C52.1 C53.1 C54.1 C55.1 C56.1 C57.1 C58.1 C59.1 C60.1 C61.1 C62.1 C63.1 C64.1 C65.1 C66.1 C67.1 C68.1 C178.1 C179.1 C180.1 C181.1 C184.1 C186.1 C188.1 C212.1 C213.1 J14.1(GND) J14.4(GND) J14.7(GND) J14.13(GND) J14.16(GND) J14.19(GND) J14.20(GND) J14.23(GND) J14.26(GND) J14.32(GND) J14.35(GND) J14.38(GND) J15.1(GND) J15.4(GND) J15.7(GND) J15.13(GND) J15.16(GND) J15.19(GND) J15.20(GND) J15.23(GND) J15.26(GND) J15.32(GND) J15.35(GND) J15.38(GND) R11.1 U8.2(GND) U8.5(DIR) U9.7(GND) U10.7(GND) U11.2(GND) U11.5(DIR) U23.7(GND)
VCCO_87_88: C49.2 C59.2 C62.2 C65.2 C188.2 R9.2 R47.2 R48.2 R49.2 R50.2 U8.1(Vcca) U9.1(VL) U10.1(VL) U11.1(Vcca) U23.1(VL)
QSFP1_INT_B: U8.3(A) ; port QSFP1_Control.IntL
QSFP1_LP_MODE: U9.5(I/O_VL4) ; port QSFP1_Control.LPMode
QSFP1_MODPRS_B: U9.2(I/O_VL1) ; port QSFP1_Control.ModPrsL
QSFP1_MODSEL_B: U9.4(I/O_VL3) ; port QSFP1_Control.ModselL
QSFP1_RESET_B: U9.3(I/O_VL2) ; port QSFP1_Control.ResetL
QSFP1_RX1N: J14.18(RX1n) ; port QSFP1_Transceivers.RX1N
QSFP1_RX1P: J14.17(RX1p) ; port QSFP1_Transceivers.RX1P
QSFP1_RX2N: J14.21(RX2n) ; port QSFP1_Transceivers.RX2N
QSFP1_RX2P: J14.22(RX2p) ; port QSFP1_Transceivers.RX2P
QSFP1_RX3N: J14.15(RX3n) ; port QSFP1_Transceivers.RX3N
QSFP1_RX3P: J14.14(RX3p) ; port QSFP1_Transceivers.RX3P
QSFP1_RX4N: J14.24(RX4n) ; port QSFP1_Transceivers.RX4N
QSFP1_RX4P: J14.25(RX4p) ; port QSFP1_Transceivers.RX4P
QSFP1_SCL: R48.1 U10.4(I/O_VL3) ; port QSFP1_Control.SCL
QSFP1_SDA: R47.1 U10.5(I/O_VL4) ; port QSFP1_Control.SDA
QSFP1_TX1N: J14.37(TX1n) ; port QSFP1_Transceivers.TX1N
QSFP1_TX1P: J14.36(TX1p) ; port QSFP1_Transceivers.TX1P
QSFP1_TX2N: J14.2(TX2n) ; port QSFP1_Transceivers.TX2N
QSFP1_TX2P: J14.3(TX2p) ; port QSFP1_Transceivers.TX2P
QSFP1_TX3N: J14.34(TX3n) ; port QSFP1_Transceivers.TX3N
QSFP1_TX3P: J14.33(TX3p) ; port QSFP1_Transceivers.TX3P
QSFP1_TX4N: J14.5(TX4n) ; port QSFP1_Transceivers.TX4N
QSFP1_TX4P: J14.6(TX4p) ; port QSFP1_Transceivers.TX4P
QSFP2_INT_B: U11.3(A) ; port QSFP2_Control.IntL
QSFP2_LP_MODE: U23.5(I/O_VL4) ; port QSFP2_Control.LPMode
QSFP2_MODPRS_B: U23.2(I/O_VL1) ; port QSFP2_Control.ModPrsL
QSFP2_MODSEL_B: U23.4(I/O_VL3) ; port QSFP2_Control.ModselL
QSFP2_RESET_B: U23.3(I/O_VL2) ; port QSFP2_Control.ResetL
QSFP2_RX1N: J15.18(RX1n) ; port QSFP2_Transceivers.RX1N
QSFP2_RX1P: J15.17(RX1p) ; port QSFP2_Transceivers.RX1P
QSFP2_RX2N: J15.21(RX2n) ; port QSFP2_Transceivers.RX2N
QSFP2_RX2P: J15.22(RX2p) ; port QSFP2_Transceivers.RX2P
QSFP2_RX3N: J15.15(RX3n) ; port QSFP2_Transceivers.RX3N
QSFP2_RX3P: J15.14(RX3p) ; port QSFP2_Transceivers.RX3P
QSFP2_RX4N: J15.24(RX4n) ; port QSFP2_Transceivers.RX4N
QSFP2_RX4P: J15.25(RX4p) ; port QSFP2_Transceivers.RX4P
QSFP2_SCL: R50.1 U10.2(I/O_VL1) ; port QSFP2_Control.SCL
QSFP2_SDA: R49.1 U10.3(I/O_VL2) ; port QSFP2_Control.SDA
QSFP2_TX1N: J15.37(TX1n) ; port QSFP2_Transceivers.TX1N
QSFP2_TX1P: J15.36(TX1p) ; port QSFP2_Transceivers.TX1P
QSFP2_TX2N: J15.2(TX2n) ; port QSFP2_Transceivers.TX2N
QSFP2_TX2P: J15.3(TX2p) ; port QSFP2_Transceivers.TX2P
QSFP2_TX3N: J15.34(TX3n) ; port QSFP2_Transceivers.TX3N
QSFP2_TX3P: J15.33(TX3p) ; port QSFP2_Transceivers.TX3P
QSFP2_TX4N: J15.5(TX4n) ; port QSFP2_Transceivers.TX4N
QSFP2_TX4P: J15.6(TX4p) ; port QSFP2_Transceivers.TX4P
QSFP_1_INT_B_3V3: J14.28(IntL) R41.1 TP32.1(PIN) U8.4(B)
QSFP_1_LP_MODE_3V3: J14.31(LPMode) TP36.1(PIN) U9.10(I/O_VCC4)
QSFP_1_MODPRS_B_3V3: J14.27(ModPrsL) R42.1 TP33.1(PIN) U9.13(I/O_VCC1)
QSFP_1_MODSEL_B_3V3: J14.8(ModselL) TP35.1(PIN) U9.11(I/O_VCC3)
QSFP_1_RESET_B_3V3: J14.9(ResetL) TP34.1(PIN) U9.12(I/O_VCC2)
QSFP_1_SCL_3V3: J14.11(SCL) R45.1 TP39.1(PIN) U10.11(I/O_VCC3)
QSFP_1_SDA_3V3: J14.12(SDA) R46.1 TP40.1(PIN) U10.10(I/O_VCC4)
QSFP_2_INT_B_3V3: J15.28(IntL) R51.1 TP41.1(PIN) U11.4(B)
QSFP_2_LP_MODE_3V3: J15.31(LPMode) TP45.1(PIN) U23.10(I/O_VCC4)
QSFP_2_MODPRS_B_3V3: J15.27(ModPrsL) R52.1 TP42.1(PIN) U23.13(I/O_VCC1)
QSFP_2_MODSEL_B_3V3: J15.8(ModselL) TP44.1(PIN) U23.11(I/O_VCC3)
QSFP_2_RESET_B_3V3: J15.9(ResetL) TP43.1(PIN) U23.12(I/O_VCC2)
QSFP_2_SCL_3V3: J15.11(SCL) R43.1 TP37.1(PIN) U10.13(I/O_VCC1)
QSFP_2_SDA_3V3: J15.12(SDA) R44.1 TP38.1(PIN) U10.12(I/O_VCC2)
QSFP_THREESTATE#: R9.1 R10.2 U9.8(~{THREESTATE}) U10.8(~{THREESTATE}) U23.8(~{THREESTATE})
NetC53_2: C53.2 C54.2 J14.30(Vcc1) L5.2
NetC55_2: C55.2 C56.2 J14.29(VccTx) L6.2
NetC57_2: C57.2 C58.2 J14.10(VccRx) L7.2
NetC178_2: C178.2 C179.2 J15.30(Vcc1) L8.2
NetC180_2: C180.2 C181.2 J15.29(VccTx) L9.2
NetC184_2: C184.2 C186.2 J15.10(VccRx) L10.2
NetMC3_48: R10.1 R11.2 ; port QSFP_THREESTATE_N_IO

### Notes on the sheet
- Level Translators
- QSFP 1
- (near QSFP1) QSFP Cage
- QSFP 2
- (near QSFP2) QSFP Cage
- Title
- Size:
- Date:
- C
- Number:
- Time:
- Revision:
- Sheet
- of

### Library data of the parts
C49 C50 C65 C66 = 001073: Partnumber: 000070; manufacturer: Kemet; ValueFloat: 1E-7; x_tolerance: 10
C51 C54 C56 C58 C67 C179 C181 C186 = 001284: Partnumber: 001284; manufacturer: Taiyo Yuden; manufacturer_pn: LMK316AB7226KL-TR; ValueFloat: 2.2E-5; id: 60625; inventory_price: 0.14; reorder_quantity: 4000; x_tolerance: 10
C52 C53 C55 C57 C68 C178 C180 C184 = 000070: Partnumber: 000070; manufacturer: Kemet; manufacturer_pn: C0402C104K8PACTU; ValueFloat: 1E-7; id: 750; inventory_price: 0.0023; reorder_quantity: 70000; x_tolerance: 10
C59 C60 C62 C63 C188 C212 = 000070: as C75 on sheet USB
C61 C64 C213 = 000480: Partnumber: 000480; manufacturer: Taiyo Yuden; ValueFloat: 1E-6; x_tolerance: 10
J14 J15 = 001782: Partnumber: 001782; manufacturer: Amphenol; id: 254667; inventory_price: 4
L5-L10 = 002331: Thin Film, 1uH, 3.1A, 50mOhm, Unshielded; Partnumber: 002331; Manufacturer: Samsung Electro-Mechanics; ValueFloat: 1E-6; Tolerance (%): 20; Description 2: 1008 (2520 Metric)
QSFP1 QSFP2 = 001781: Partnumber: 001781; manufacturer: Amphenol; manufacturer_pn: U95-T111-1001; id: 254666; inventory_price: 3.5
R9 R11 = 001521: Thick-film resistor; Manufacturer: Vishay; partnumber: 001521; Description 2: SM-0402, 1%, 1/16W; ValueFloat: 10000; Tolerance (%): 1; x_lifecycle_status: Production
R10 = 001713: Partnumber: 001713; manufacturer: Vishay; manufacturer_pn: CRCW04020000Z0EDC; id: 219362; inventory_price: 0.004; reorder_quantity: 20000; x_tolerance: 1
R41-R52 = 001008: Partnumber: 001008; manufacturer: Vishay; ValueFloat: 4750; x_tolerance: 1
TP32-TP45 = TESTPOINT-SMD40: Test point, surface-mount, 40mil
U8 U11 = 002140: Level Translator, 0.65V - 3.6V, Direction Control; Partnumber: 002140; Manufacturer: Texas Instruments; Description 2: Single Bit, Dual Supplies
U9 U10 U23 = 000178: Partnumber: 000178; manufacturer: Maxim

## Sheet Expansion-MC1.SchDoc: BRK1900 - Expansion MC1
size C; Organization: Opal Kelly; Address1: 13500 SW 72nd Ave STE 100; Address2: Portland, OR  97223; Address3: 217.391.3724; Address4: http://www.opalkelly.com; DocumentNumber: 2; Revision: 1; SheetNumber: 2; SheetTotal: 11; PageSetup: Record=PageOptions¦CenterHorizontal=True¦CenterVertical=True¦PrintScale=0.52¦XCorrection=1.00¦YCorrection=1.00¦PrintKind=0¦BorderSize=5000000¦LeftOffset=0¦BottomOffset=0¦Orientation=2¦PaperLength=1000¦PaperWidth=1000¦Scale=100¦PaperSource=7¦PrintQuality=-4¦MediaType=1¦DitherType=10¦PaperKind=Letter¦PrintScaleMode=1
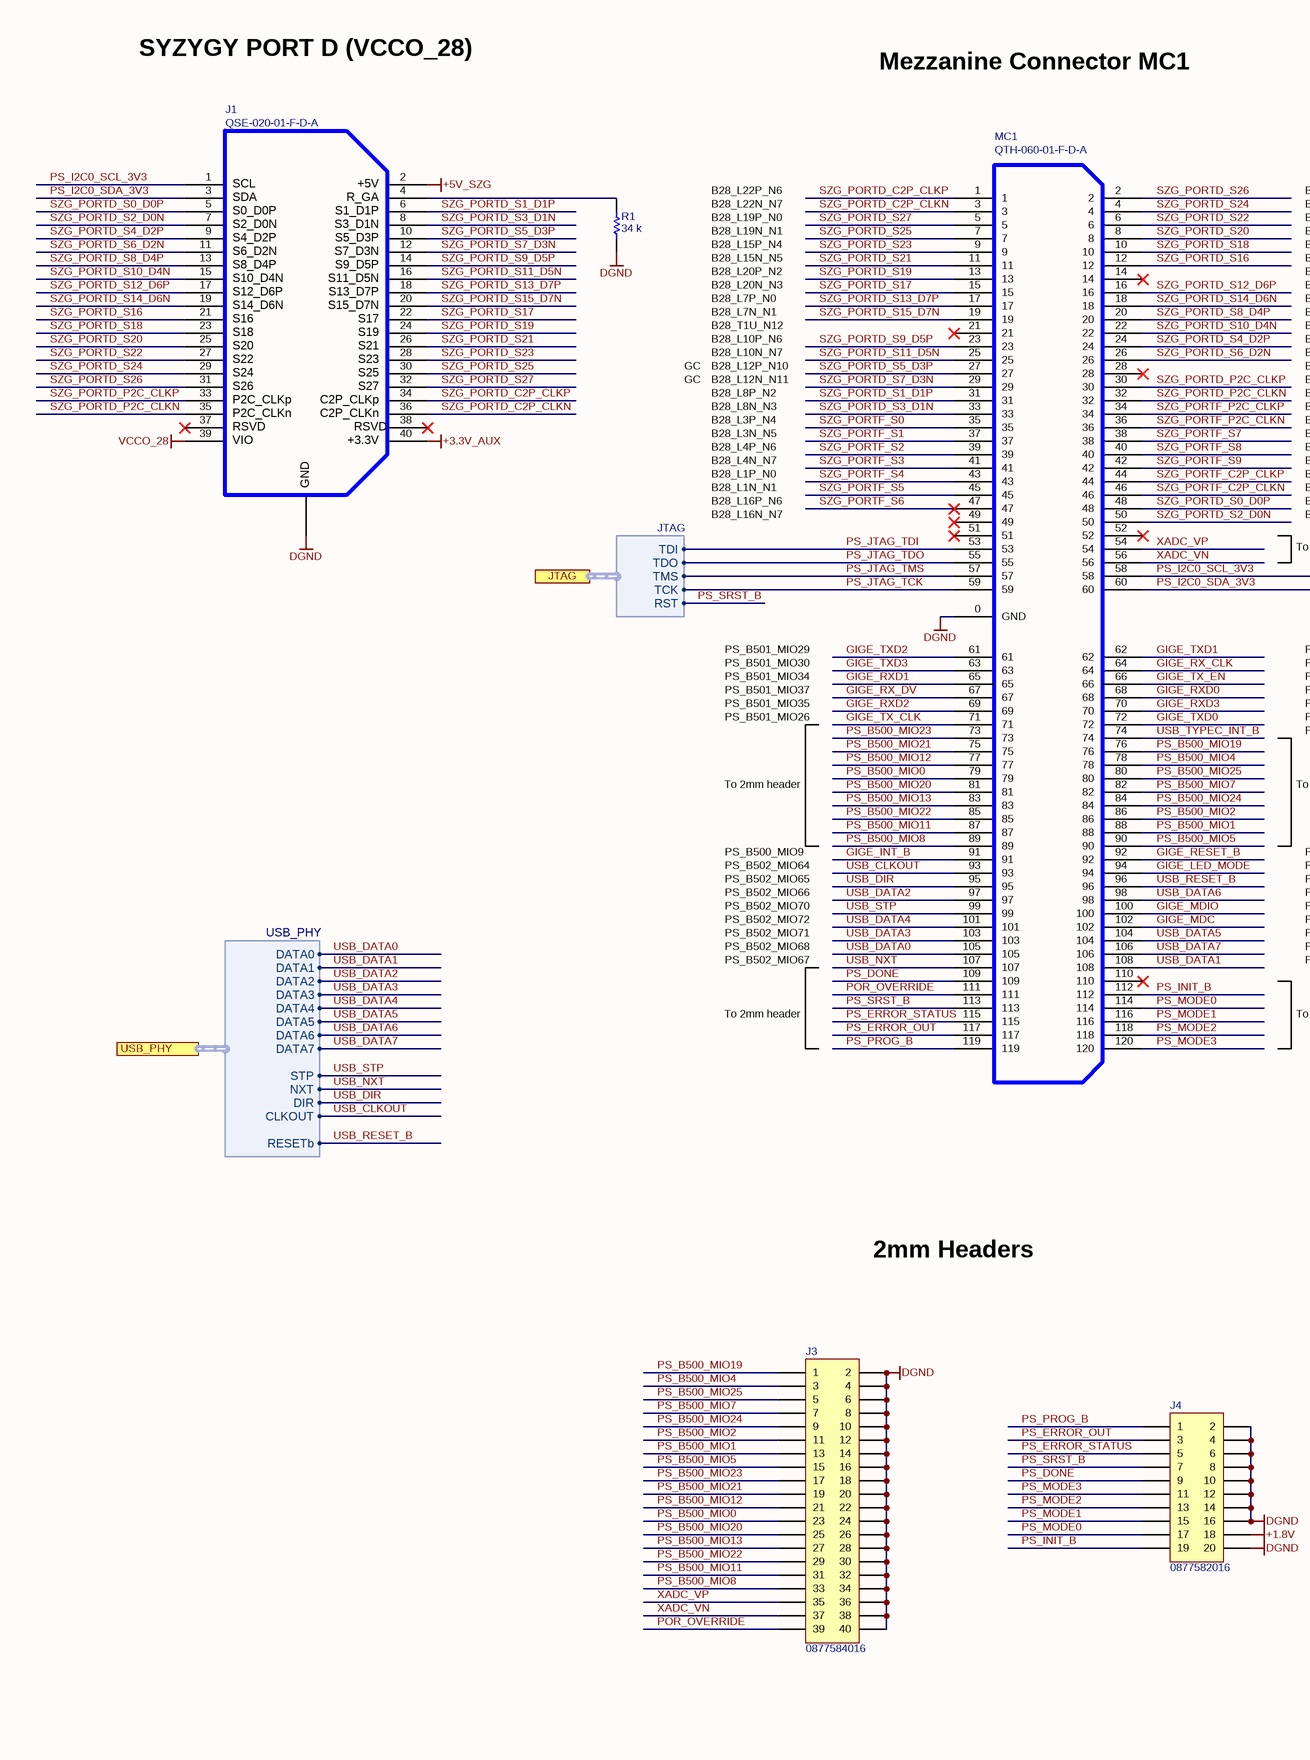
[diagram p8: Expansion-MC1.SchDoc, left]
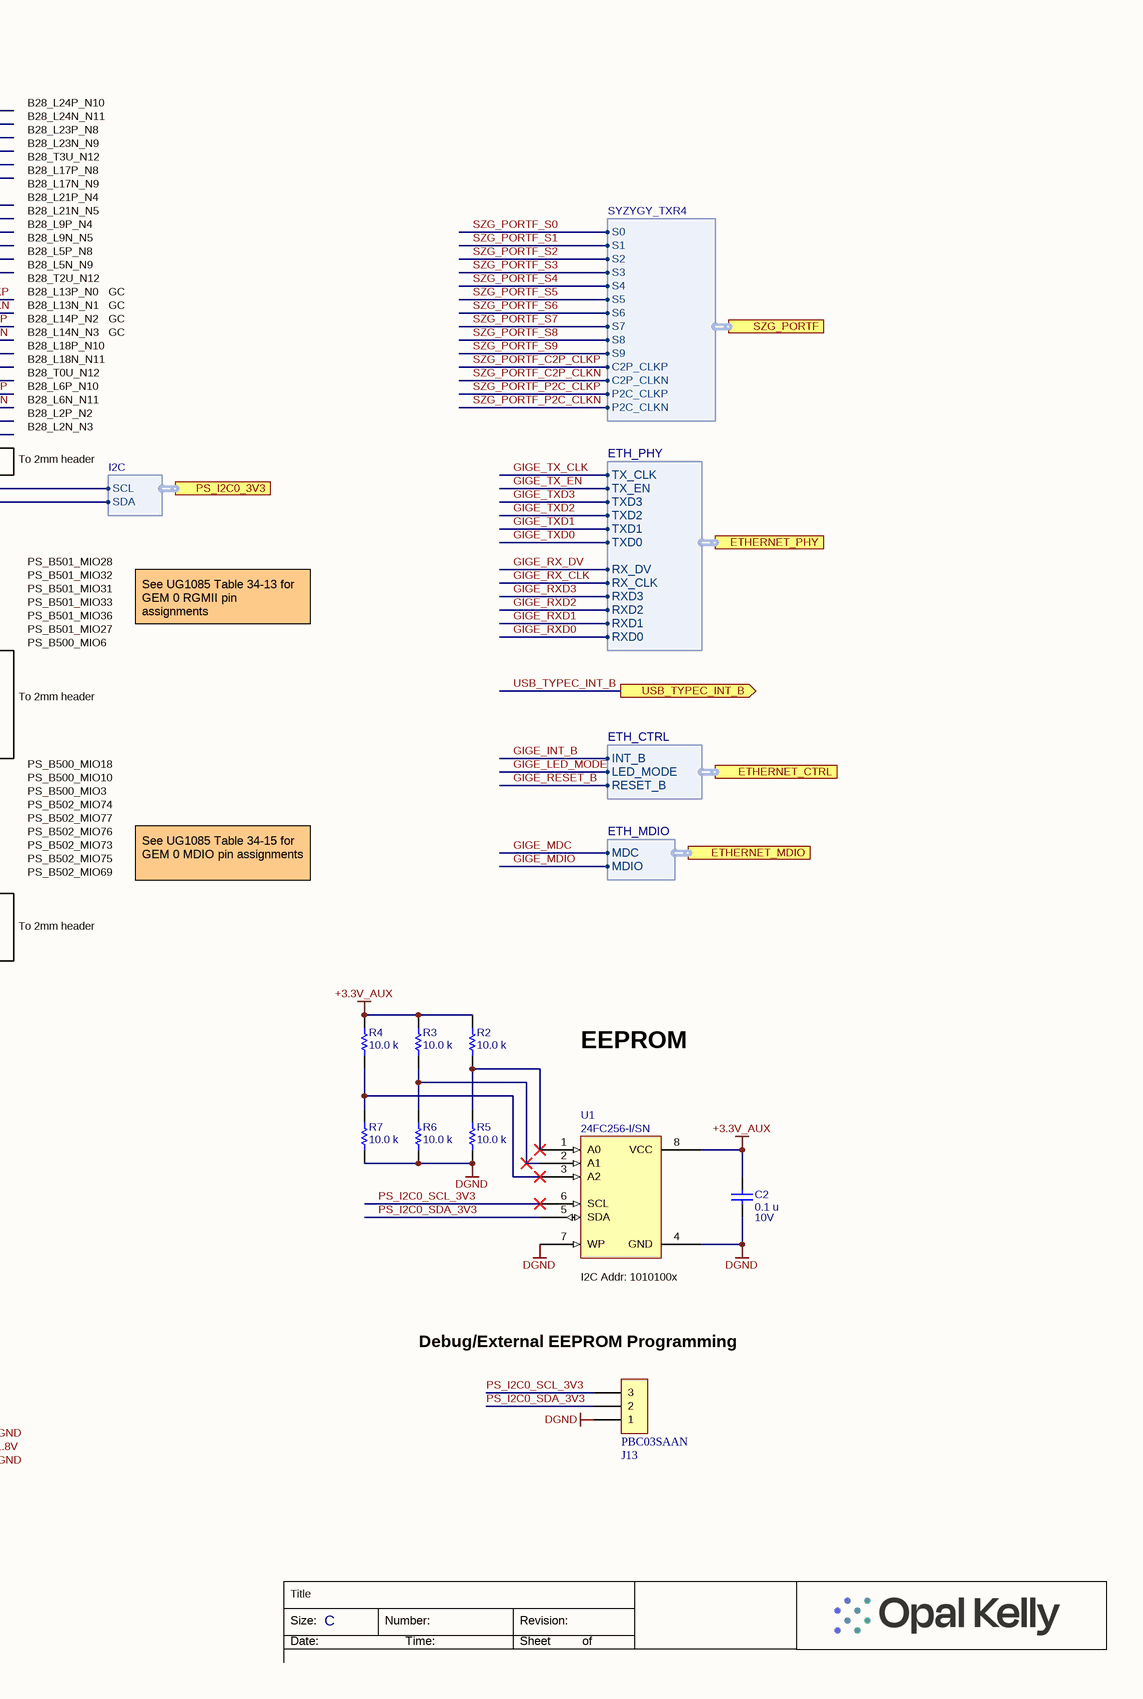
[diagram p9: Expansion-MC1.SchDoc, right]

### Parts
C2  value 0.1 u  Voltage: 10V  [CAPC1005X06A]  (hidden comment: C0402C104K8PACTU)
J1  QSE-020-01-F-D-A  [QSE-020-01-X-D-A-L-SYZYGY]
J3  0877584016  [HDR2X20-2MM]
J4  0877582016  [HDR2X10-2MM]
J13  PBC03SAAN  [HDR1X3]
MC1  QTH-060-01-F-D-A  [QTH-060-01-X-D]
R1  value 34 k  [RESC1005X06A]  (hidden comment: CRCW040234K0FKED)
R2  value 10.0 k  [RESC1005X06A]  (hidden comment: CRCW040210K0FKED)
R3  value 10.0 k  [RESC1005X06A]  (hidden comment: CRCW040210K0FKED)
R4  value 10.0 k  [RESC1005X06A]  (hidden comment: CRCW040210K0FKED)
R5  value 10.0 k  [RESC1005X06A]  (hidden comment: CRCW040210K0FKED)
R6  value 10.0 k  [RESC1005X06A]  (hidden comment: CRCW040210K0FKED)
R7  value 10.0 k  [RESC1005X06A]  (hidden comment: CRCW040210K0FKED)
U1  24FC256-I/SN  [SO-G8]

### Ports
ETHERNET_CTRL (harness ETH_CTRL), ETHERNET_MDIO (harness ETH_MDIO), ETHERNET_PHY (harness ETH_PHY), JTAG (harness JTAG), PS_I2C0_3V3 (harness I2C), SZG_PORTF (harness SYZYGY_TXR4), USB_PHY (harness USB_PHY), USB_TYPEC_INT_B (out)

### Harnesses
I2C: SCL, SDA
SYZYGY_TXR4: S0, S1, S2, S3, S4, S5, S6, S7, S8, S9, C2P_CLKP, C2P_CLKN, P2C_CLKP, P2C_CLKN
ETH_PHY: TX_CLK, TX_EN, TXD3, TXD2, TXD1, TXD0, RX_DV, RX_CLK, RXD3, RXD2, RXD1, RXD0
ETH_CTRL: INT_B, LED_MODE, RESET_B
ETH_MDIO: MDC, MDIO
USB_PHY: DATA0, DATA1, DATA2, DATA3, DATA4, DATA5, DATA6, DATA7, STP, NXT, DIR, CLKOUT, RESETb
JTAG: TDI, TDO, TCK, TMS, RST

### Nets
+1.8V: J4.18
+3.3V_AUX: C2.2 J1.40 R2.2 R3.2 R4.2 U1.8(VCC)
+5V_SZG: J1.2
DGND: C2.1 J1.0 J3.2 J3.4 J3.6 J3.8 J3.10 J3.12 J3.14 J3.16 J3.18 J3.20 J3.22 J3.24 J3.26 J3.28 J3.30 J3.32 J3.34 J3.36 J3.38 J3.40 J4.2 J4.4 J4.6 J4.8 J4.10 J4.12 J4.14 J4.16 J4.20 J13.1 MC1.0(GND) R1.1 R5.1 R6.1 R7.1 U1.4(GND) U1.7(WP)
VCCO_28: J1.39
GIGE_INT_B: MC1.91 ; port ETHERNET_CTRL.INT_B
GIGE_LED_MODE: MC1.94 ; port ETHERNET_CTRL.LED_MODE
GIGE_MDC: MC1.102 ; port ETHERNET_MDIO.MDC
GIGE_MDIO: MC1.100 ; port ETHERNET_MDIO.MDIO
GIGE_RESET_B: MC1.92 ; port ETHERNET_CTRL.RESET_B
GIGE_RX_CLK: MC1.64 ; port ETHERNET_PHY.RX_CLK
GIGE_RX_DV: MC1.67 ; port ETHERNET_PHY.RX_DV
GIGE_RXD0: MC1.68 ; port ETHERNET_PHY.RXD0
GIGE_RXD1: MC1.65 ; port ETHERNET_PHY.RXD1
GIGE_RXD2: MC1.69 ; port ETHERNET_PHY.RXD2
GIGE_RXD3: MC1.70 ; port ETHERNET_PHY.RXD3
GIGE_TX_CLK: MC1.71 ; port ETHERNET_PHY.TX_CLK
GIGE_TX_EN: MC1.66 ; port ETHERNET_PHY.TX_EN
GIGE_TXD0: MC1.72 ; port ETHERNET_PHY.TXD0
GIGE_TXD1: MC1.62 ; port ETHERNET_PHY.TXD1
GIGE_TXD2: MC1.61 ; port ETHERNET_PHY.TXD2
GIGE_TXD3: MC1.63 ; port ETHERNET_PHY.TXD3
POR_OVERRIDE: J3.39 MC1.111
PS_B500_MIO0: J3.23 MC1.79
PS_B500_MIO1: J3.13 MC1.88
PS_B500_MIO2: J3.11 MC1.86
PS_B500_MIO4: J3.3 MC1.78
PS_B500_MIO5: J3.15 MC1.90
PS_B500_MIO7: J3.7 MC1.82
PS_B500_MIO8: J3.33 MC1.89
PS_B500_MIO11: J3.31 MC1.87
PS_B500_MIO12: J3.21 MC1.77
PS_B500_MIO13: J3.27 MC1.83
PS_B500_MIO19: J3.1 MC1.76
PS_B500_MIO20: J3.25 MC1.81
PS_B500_MIO21: J3.19 MC1.75
PS_B500_MIO22: J3.29 MC1.85
PS_B500_MIO23: J3.17 MC1.73
PS_B500_MIO24: J3.9 MC1.84
PS_B500_MIO25: J3.5 MC1.80
PS_DONE: J4.9 MC1.109
PS_ERROR_OUT: J4.3 MC1.117
PS_ERROR_STATUS: J4.5 MC1.115
PS_I2C0_SCL_3V3: J1.1 J13.3 MC1.58 U1.6(SCL) ; port PS_I2C0_3V3.SCL
PS_I2C0_SDA_3V3: J1.3 J13.2 MC1.60 U1.5(SDA) ; port PS_I2C0_3V3.SDA
PS_INIT_B: J4.19 MC1.112
PS_JTAG_TCK: MC1.59 ; port JTAG.TCK
PS_JTAG_TDI: MC1.53 ; port JTAG.TDI
PS_JTAG_TDO: MC1.55 ; port JTAG.TDO
PS_JTAG_TMS: MC1.57 ; port JTAG.TMS
PS_MODE0: J4.17 MC1.114
PS_MODE1: J4.15 MC1.116
PS_MODE2: J4.13 MC1.118
PS_MODE3: J4.11 MC1.120
PS_PROG_B: J4.1 MC1.119
PS_SRST_B: J4.7 MC1.113 ; port JTAG.RST
SZG_PORTD_C2P_CLKN: J1.36 MC1.3
SZG_PORTD_C2P_CLKP: J1.34 MC1.1
SZG_PORTD_P2C_CLKN: J1.35 MC1.32
SZG_PORTD_P2C_CLKP: J1.33 MC1.30
SZG_PORTD_S0_D0P: J1.5 MC1.48
SZG_PORTD_S1_D1P: J1.6 MC1.31
SZG_PORTD_S2_D0N: J1.7 MC1.50
SZG_PORTD_S3_D1N: J1.8 MC1.33
SZG_PORTD_S4_D2P: J1.9 MC1.24
SZG_PORTD_S5_D3P: J1.10 MC1.27
SZG_PORTD_S6_D2N: J1.11 MC1.26
SZG_PORTD_S7_D3N: J1.12 MC1.29
SZG_PORTD_S8_D4P: J1.13 MC1.20
SZG_PORTD_S9_D5P: J1.14 MC1.23
SZG_PORTD_S10_D4N: J1.15 MC1.22
SZG_PORTD_S11_D5N: J1.16 MC1.25
SZG_PORTD_S12_D6P: J1.17 MC1.16
SZG_PORTD_S13_D7P: J1.18 MC1.17
SZG_PORTD_S14_D6N: J1.19 MC1.18
SZG_PORTD_S15_D7N: J1.20 MC1.19
SZG_PORTD_S16: J1.21 MC1.12
SZG_PORTD_S17: J1.22 MC1.15
SZG_PORTD_S18: J1.23 MC1.10
SZG_PORTD_S19: J1.24 MC1.13
SZG_PORTD_S20: J1.25 MC1.8
SZG_PORTD_S21: J1.26 MC1.11
SZG_PORTD_S22: J1.27 MC1.6
SZG_PORTD_S23: J1.28 MC1.9
SZG_PORTD_S24: J1.29 MC1.4
SZG_PORTD_S25: J1.30 MC1.7
SZG_PORTD_S26: J1.31 MC1.2
SZG_PORTD_S27: J1.32 MC1.5
SZG_PORTF_C2P_CLKN: MC1.46 ; port SZG_PORTF.C2P_CLKN
SZG_PORTF_C2P_CLKP: MC1.44 ; port SZG_PORTF.C2P_CLKP
SZG_PORTF_P2C_CLKN: MC1.36 ; port SZG_PORTF.P2C_CLKN
SZG_PORTF_P2C_CLKP: MC1.34 ; port SZG_PORTF.P2C_CLKP
SZG_PORTF_S0: MC1.35 ; port SZG_PORTF.S0
SZG_PORTF_S1: MC1.37 ; port SZG_PORTF.S1
SZG_PORTF_S2: MC1.39 ; port SZG_PORTF.S2
SZG_PORTF_S3: MC1.41 ; port SZG_PORTF.S3
SZG_PORTF_S4: MC1.43 ; port SZG_PORTF.S4
SZG_PORTF_S5: MC1.45 ; port SZG_PORTF.S5
SZG_PORTF_S6: MC1.47 ; port SZG_PORTF.S6
SZG_PORTF_S7: MC1.38 ; port SZG_PORTF.S7
SZG_PORTF_S8: MC1.40 ; port SZG_PORTF.S8
SZG_PORTF_S9: MC1.42 ; port SZG_PORTF.S9
USB_CLKOUT: MC1.93 ; port USB_PHY.CLKOUT
USB_DATA0: MC1.105 ; port USB_PHY.DATA0
USB_DATA1: MC1.108 ; port USB_PHY.DATA1
USB_DATA2: MC1.97 ; port USB_PHY.DATA2
USB_DATA3: MC1.103 ; port USB_PHY.DATA3
USB_DATA4: MC1.101 ; port USB_PHY.DATA4
USB_DATA5: MC1.104 ; port USB_PHY.DATA5
USB_DATA6: MC1.98 ; port USB_PHY.DATA6
USB_DATA7: MC1.106 ; port USB_PHY.DATA7
USB_DIR: MC1.95 ; port USB_PHY.DIR
USB_NXT: MC1.107 ; port USB_PHY.NXT
USB_RESET_B: MC1.96 ; port USB_PHY.RESETb
USB_STP: MC1.99 ; port USB_PHY.STP
USB_TYPEC_INT_B: MC1.74 ; port USB_TYPEC_INT_B
XADC_VN: J3.37 MC1.56
XADC_VP: J3.35 MC1.54
NetJ1_4: J1.4 R1.2
NetR2_1: R2.1 R5.2 U1.1(A0)
NetR3_1: R3.1 R6.2 U1.2(A1)
NetR4_1: R4.1 R7.2 U1.3(A2)

Not connected (* = marked no-connect by the designer): J1 37* 38*; MC1 14* 21* 28* 49* 51* 52* 110*

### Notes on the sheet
- SYZYGY PORT D (VCCO_28)
- Mezzanine Connector MC1
- B28_L22P_N6
- B28_L24P_N10
- B28_L22N_N7
- B28_L19P_N0
- B28_L19N_N1
- B28_L15P_N4
- B28_L15N_N5
- B28_L24N_N11
- B28_L23P_N8
- B28_L23N_N9
- B28_T3U_N12
- B28_L17P_N8
- B28_L20P_N2
- B28_L20N_N3
- B28_L7P_N0
- B28_L7N_N1
- B28_T1U_N12
- B28_L17N_N9
- B28_L21P_N4
- B28_L21N_N5
- B28_L9P_N4
- B28_L9N_N5
- GC
- B28_L10P_N6
- B28_L10N_N7
- B28_L12P_N10
- B28_L12N_N11
- B28_L8P_N2
- B28_L5P_N8
- B28_L5N_N9
- B28_T2U_N12
- B28_L13P_N0
- B28_L13N_N1
- B28_L8N_N3
- B28_L3P_N4
- B28_L3N_N5
- B28_L4P_N6
- B28_L4N_N7
- B28_L14P_N2
- B28_L14N_N3
- B28_L18P_N10
- B28_L18N_N11
- B28_T0U_N12
- B28_L1P_N0
- B28_L1N_N1
- B28_L16P_N6
- B28_L16N_N7
- B28_L6P_N10
- B28_L6N_N11
- B28_L2P_N2
- B28_L2N_N3
- To 2mm header
- PS_B501_MIO29
- PS_B501_MIO30
- PS_B501_MIO28
- PS_B501_MIO32
- PS_B501_MIO34
- PS_B501_MIO37
- PS_B501_MIO35
- PS_B501_MIO26
- PS_B501_MIO31
- PS_B501_MIO33
- PS_B501_MIO36
- PS_B501_MIO27
- PS_B500_MIO6
- See UG1085 Table 34-13 for GEM 0 RGMII pin assignments
- PS_B500_MIO9
- PS_B502_MIO64
- PS_B500_MIO18
- PS_B500_MIO10
- PS_B502_MIO66
- PS_B502_MIO70
- PS_B502_MIO72
- PS_B502_MIO71
- PS_B502_MIO65
- PS_B502_MIO74
- PS_B502_MIO77
- PS_B502_MIO76
- PS_B502_MIO73
- PS_B500_MIO3
- PS_B502_MIO68
- PS_B502_MIO67
- PS_B502_MIO75
- PS_B502_MIO69
- See UG1085 Table 34-15 for GEM 0 MDIO pin assignments
- EEPROM
- 2mm Headers
- (near U1) I2C Addr: 1010100x
- (near J13) Debug/External EEPROM Programming
- Title
- Size:
- Date:
- C
- Number:
- Time:
- Revision:
- Sheet
- of

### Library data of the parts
C2 = 000070: Ceramic capacitor; Partnumber: 000070; manufacturer: Kemet; ValueFloat: 1E-7; x_tolerance: 10
J1 = 001604: 0.8mm hi-speed, high-density header (male); Manufacturer: Samtec; partnumber: 001604; Description 2: 40-pin, ground protection in middle
J3 = 000583: Partnumber: 000583; manufacturer: Molex
J4 = 001338: Partnumber: 001338; manufacturer: Molex
J13 = 001173: Partnumber: 001173; Manufacturer: Sullins Electronics Corp.; Description 2: Male, 0.1", 3-pos
MC1 = 000855: 0.5mm Double Row High Speed Socket Assembly; Manufacturer: Samtec; partnumber: 000855; Description 2: 180 Pins - HSMC Host Compatible - 9GHz
R1 = 001551: Partnumber: 001551; manufacturer: Vishay; ValueFloat: 34000; x_tolerance: 1
R2-R7 = 001521: Thick-film resistor; Partnumber: 001521; manufacturer: Vishay; ValueFloat: 10000; x_tolerance: 1
U1 = 000842: EEPROM; Partnumber: 000842; manufacturer: Microchip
